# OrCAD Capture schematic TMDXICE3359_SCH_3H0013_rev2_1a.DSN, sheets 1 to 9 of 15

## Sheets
1 P13_Host Expansion & MMC0 & LCD: size C; title: TMDXICE3359; rev: 2.0A; company: Texas Instruments; note: AM335X_ICE_3H0013_2V0A.dsn; note: ARM MPU BU; note: 12500 TI BLVD MS8638
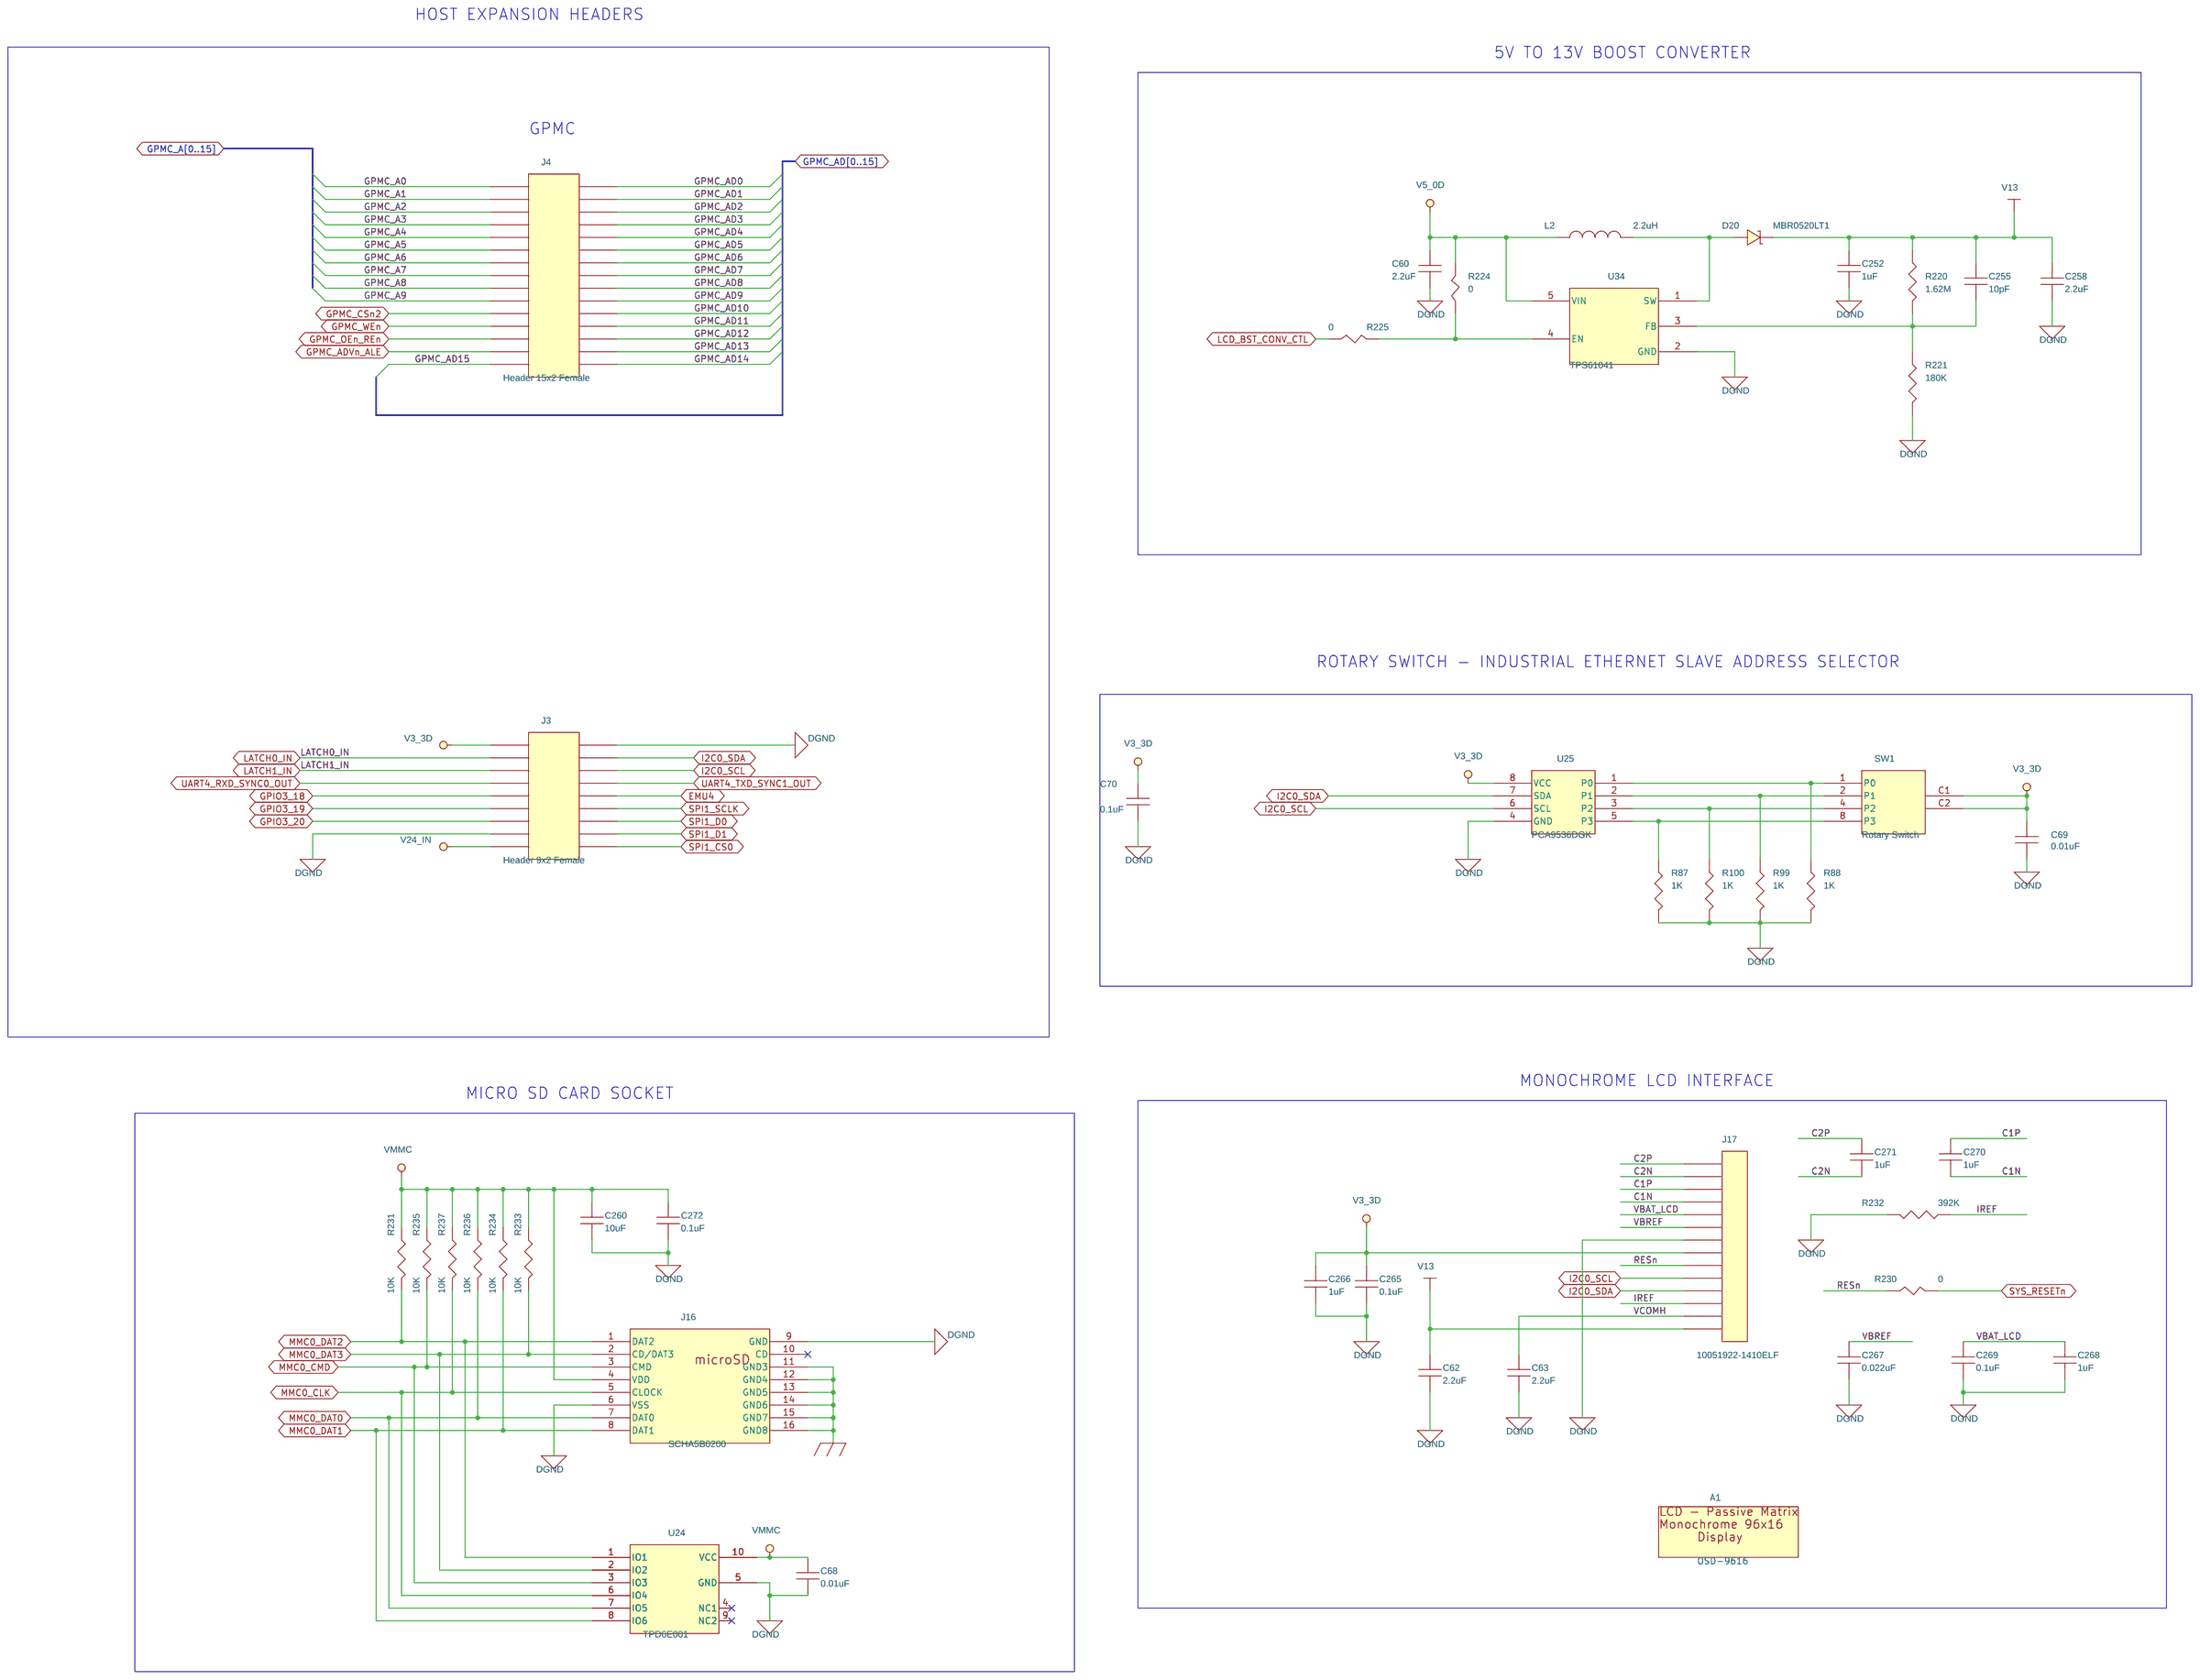
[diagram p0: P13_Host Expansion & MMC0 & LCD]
2 P12_Ethernet1: size C
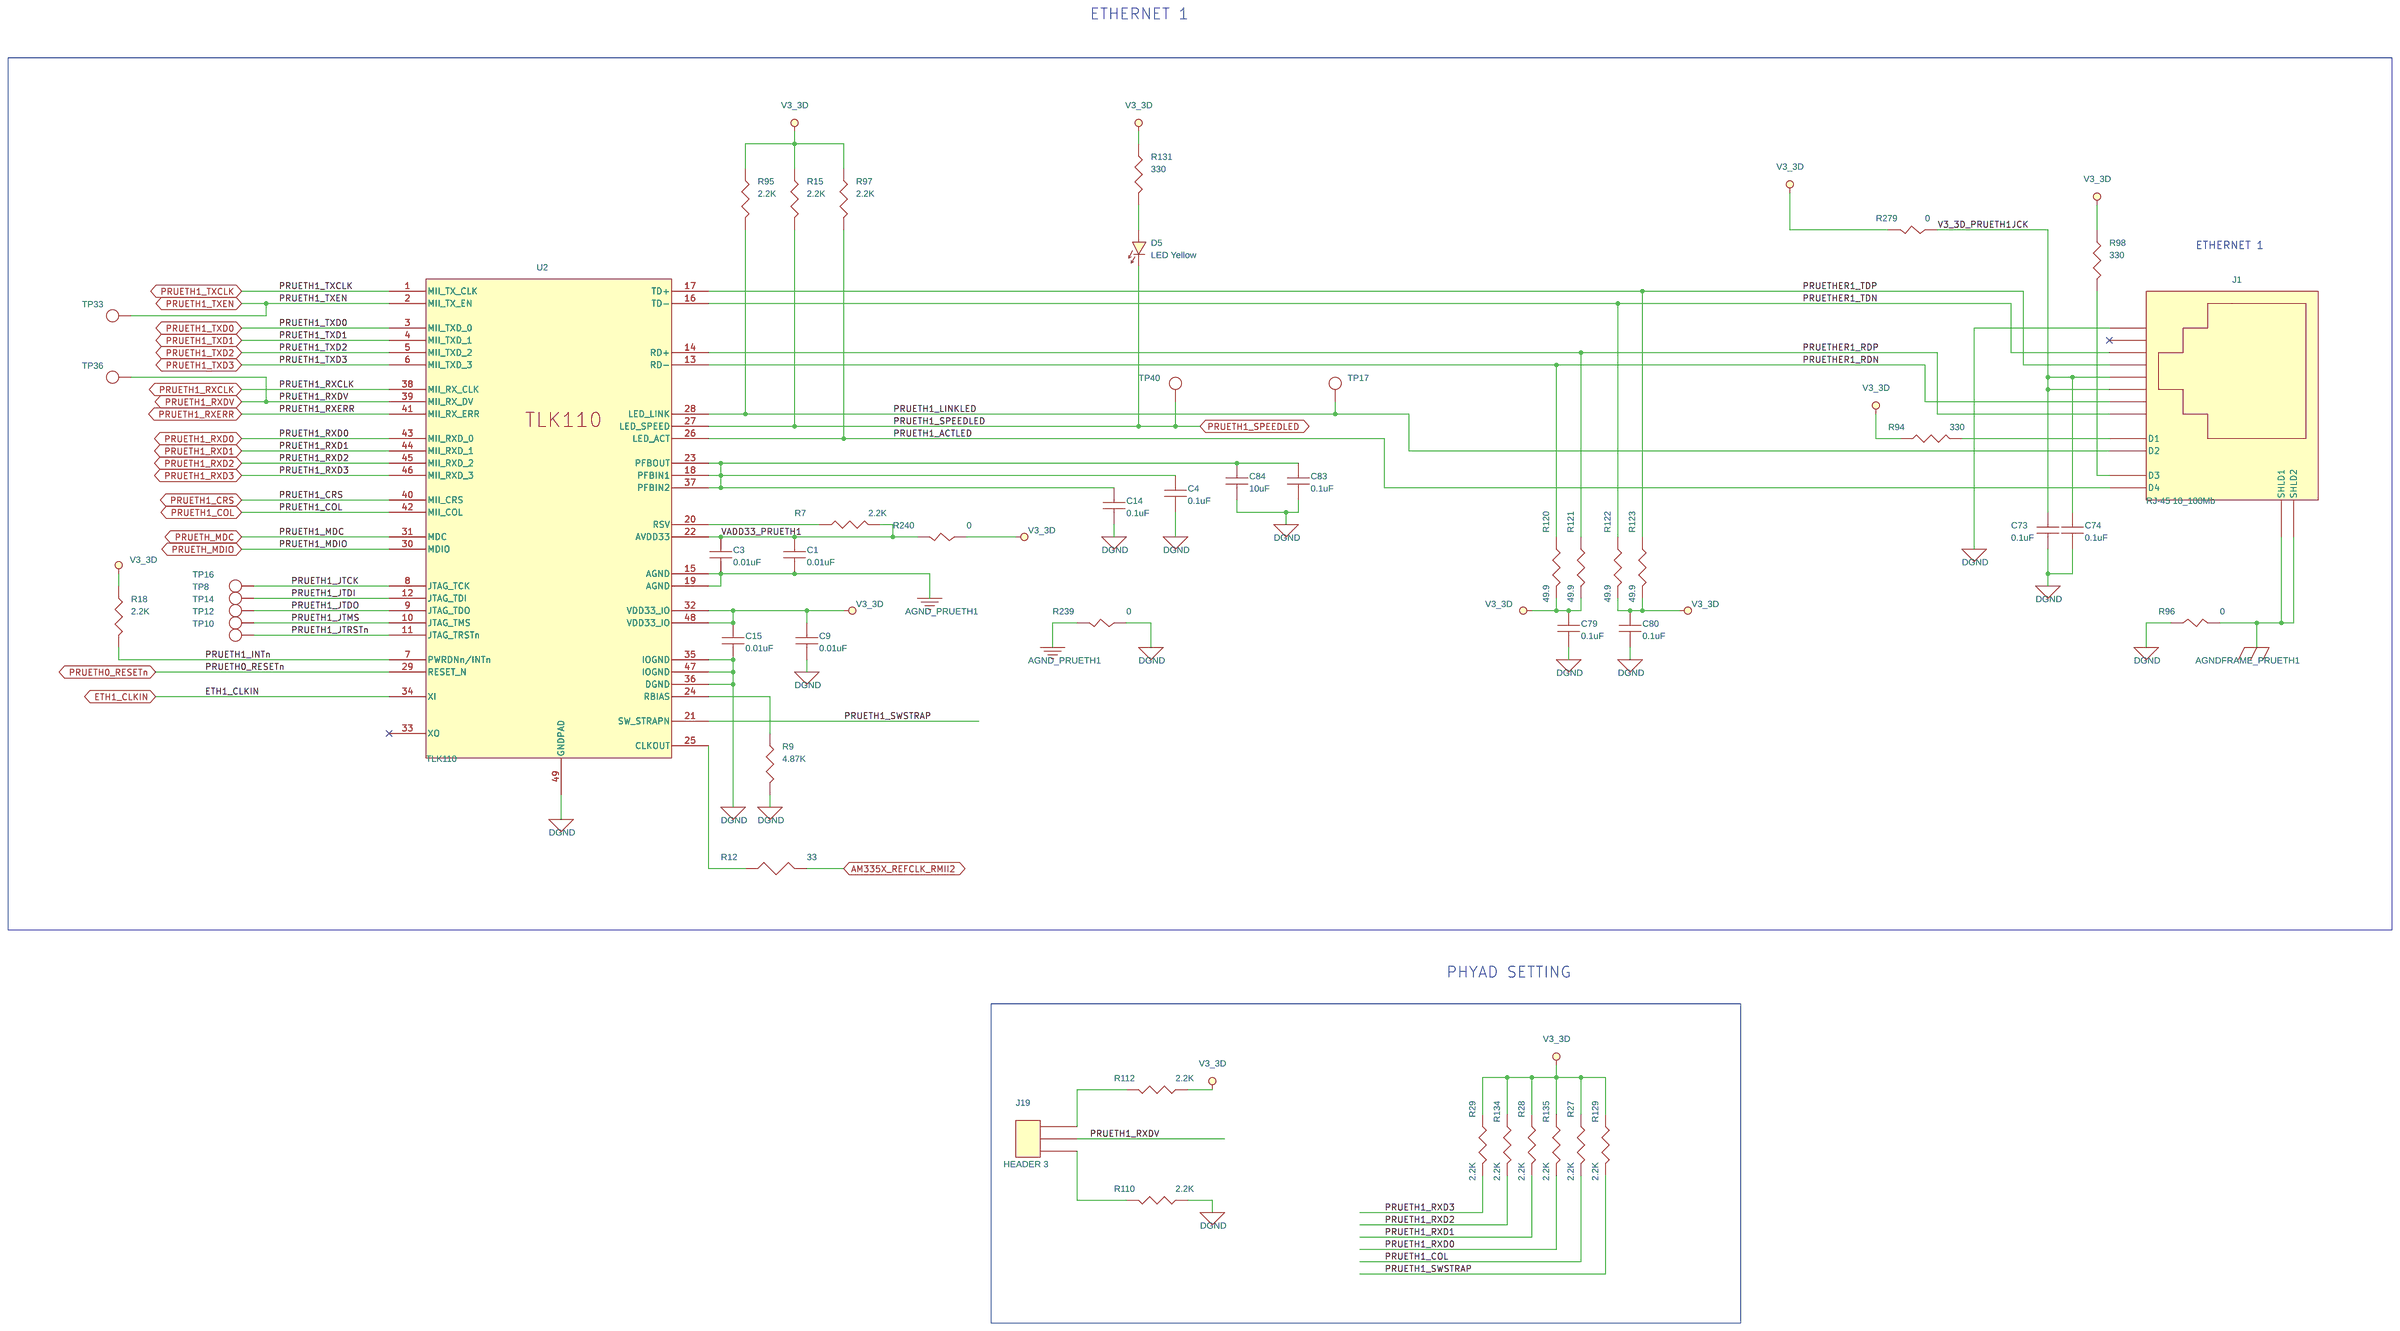
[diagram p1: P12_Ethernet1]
3 P11_Ethernet0: size C
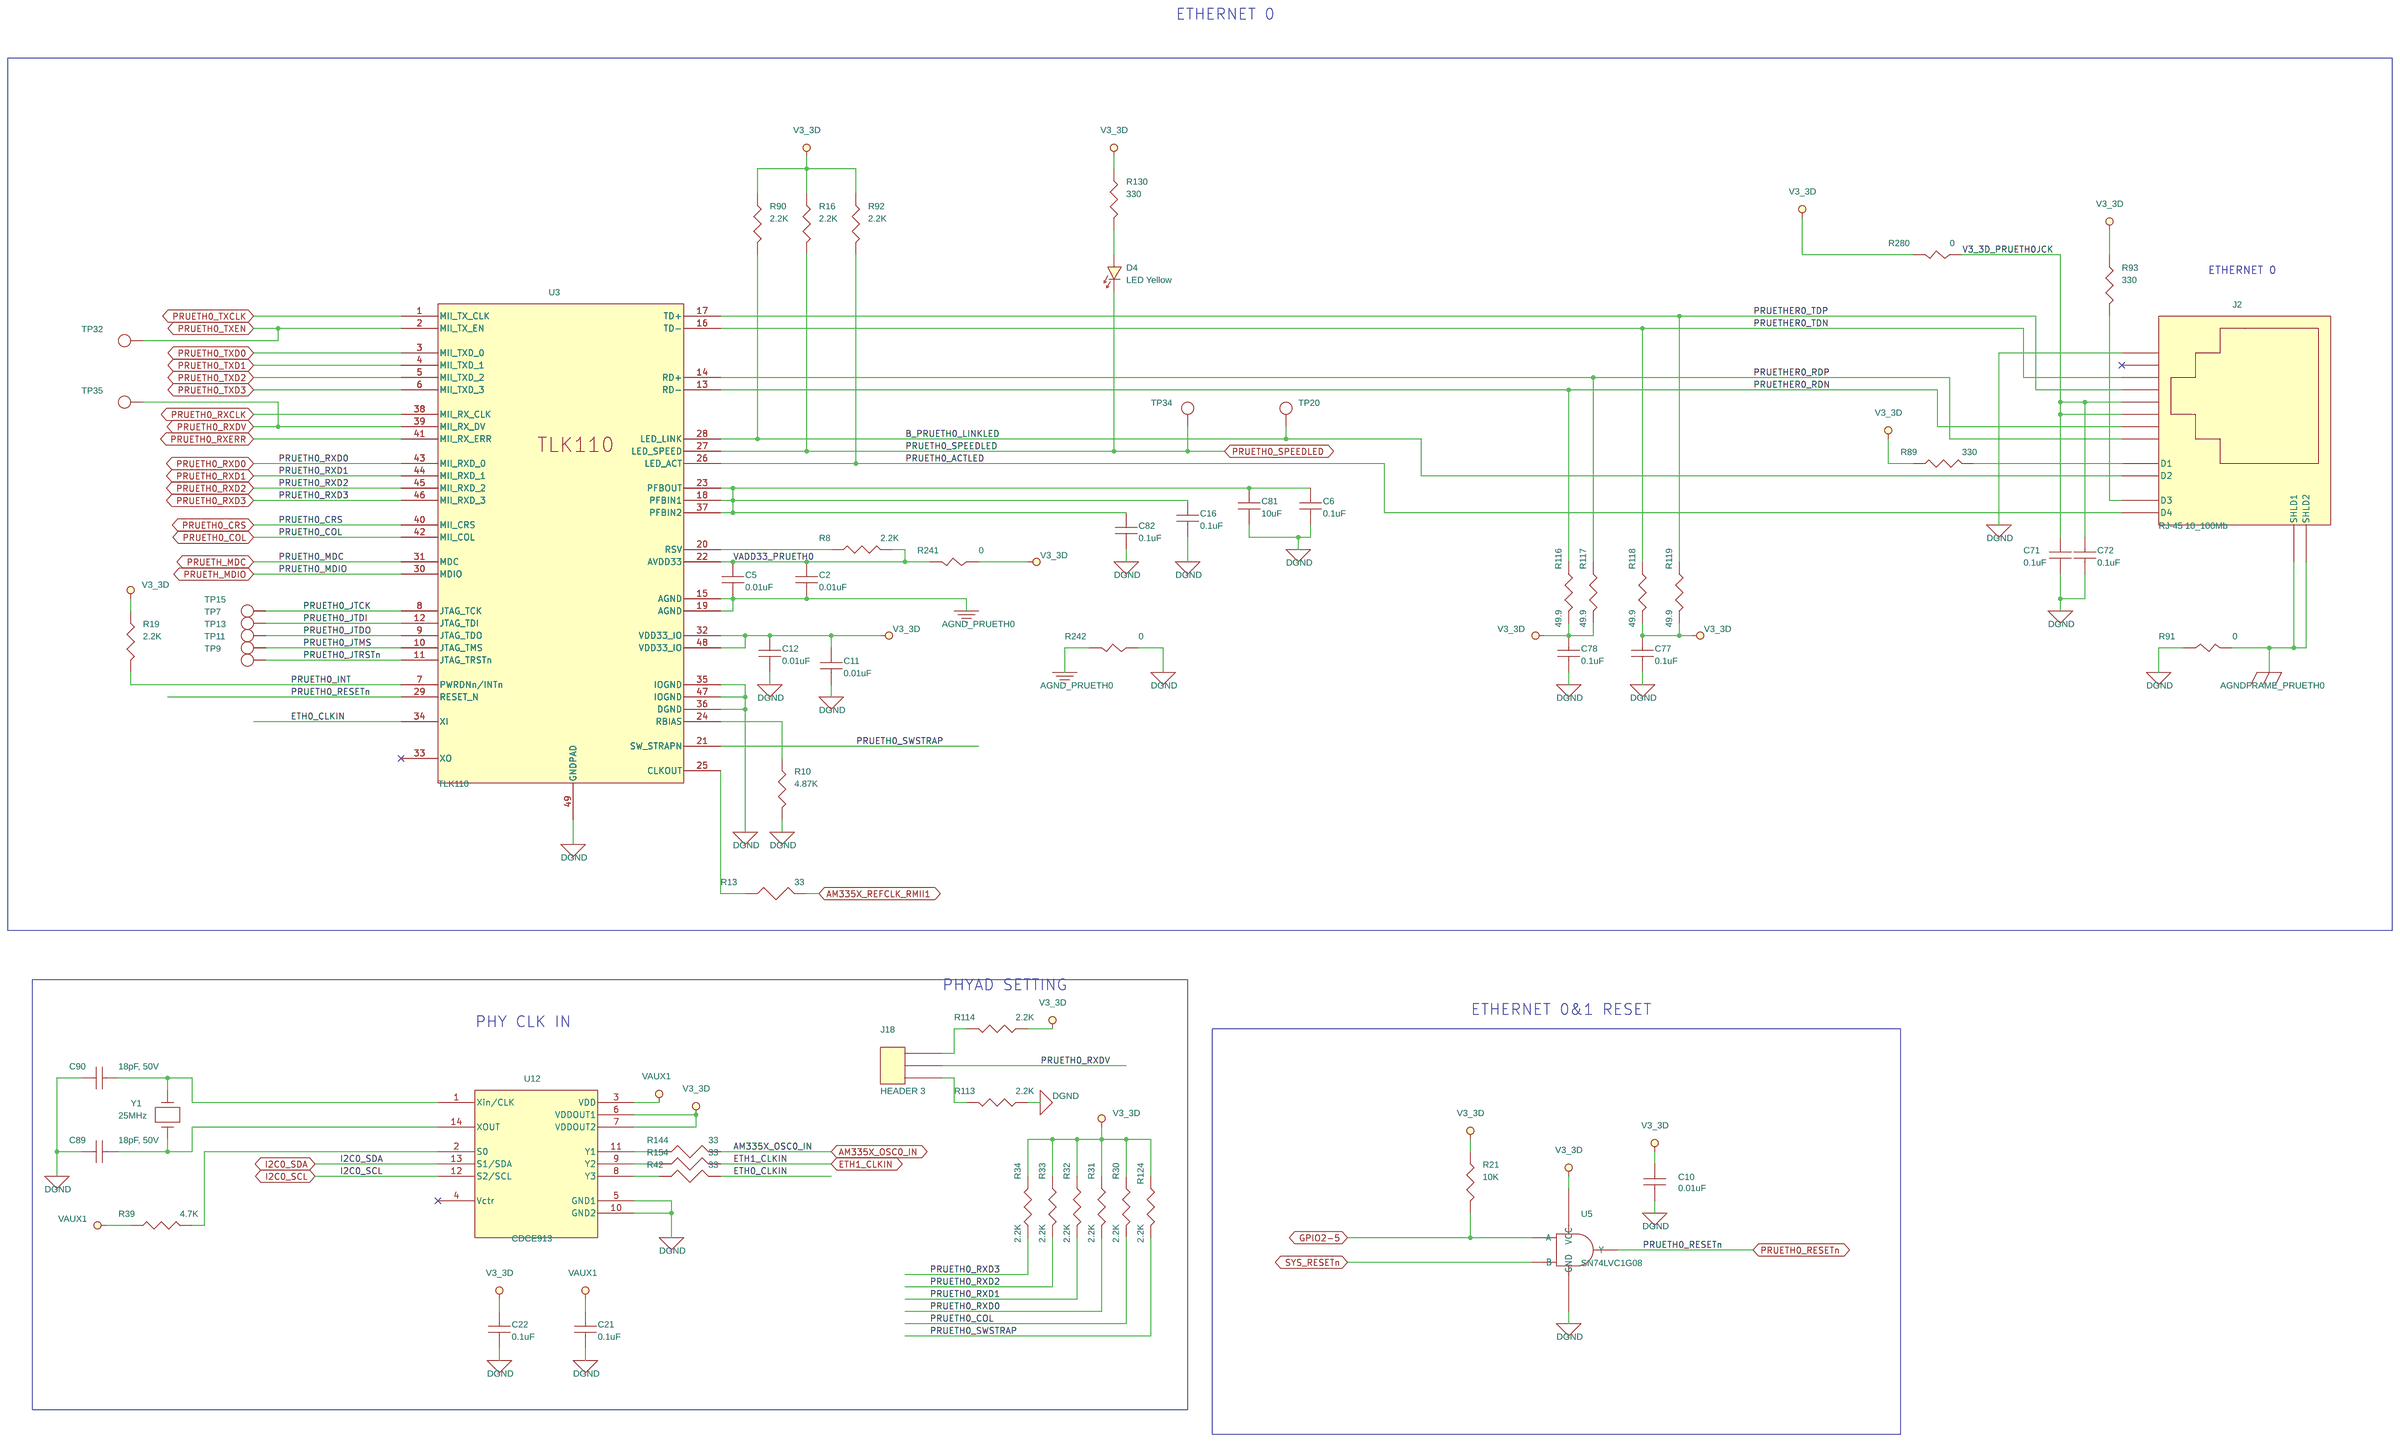
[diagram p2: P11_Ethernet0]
4 P10_PRU_CPSW_ETHERNET_MUX: size C
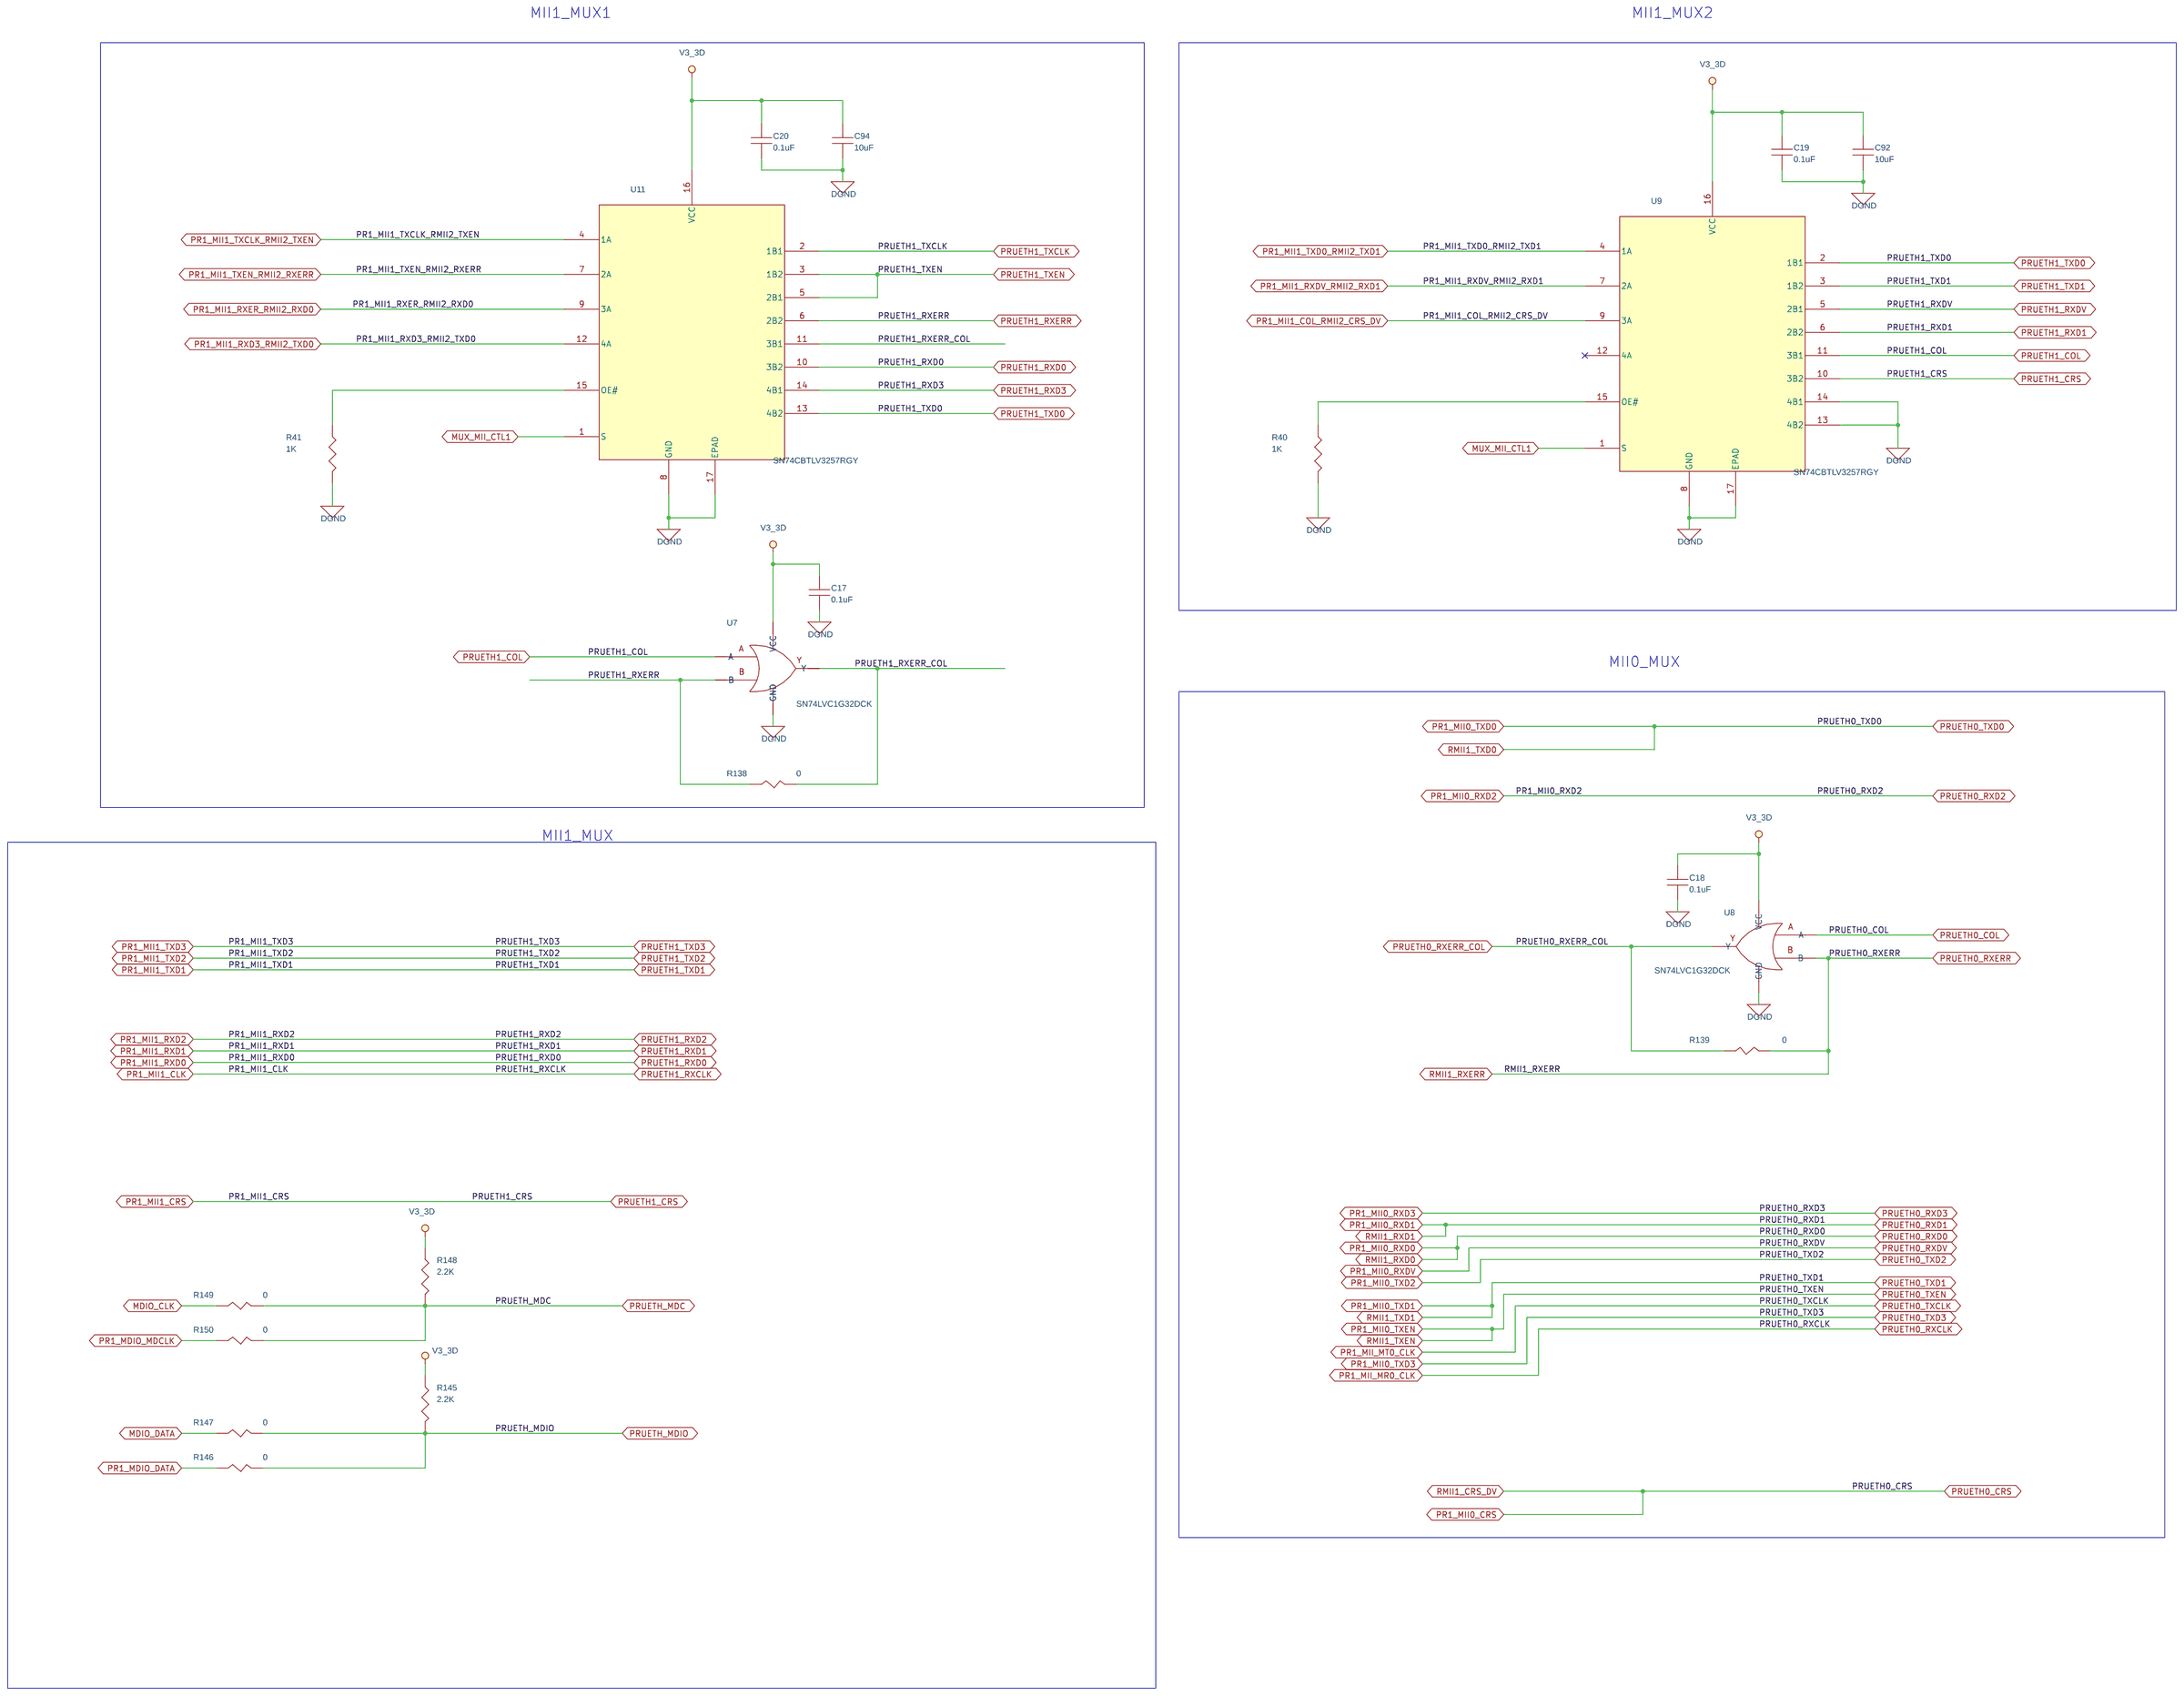
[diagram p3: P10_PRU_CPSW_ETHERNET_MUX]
5 P09_CAN & PROFI BUS: size C
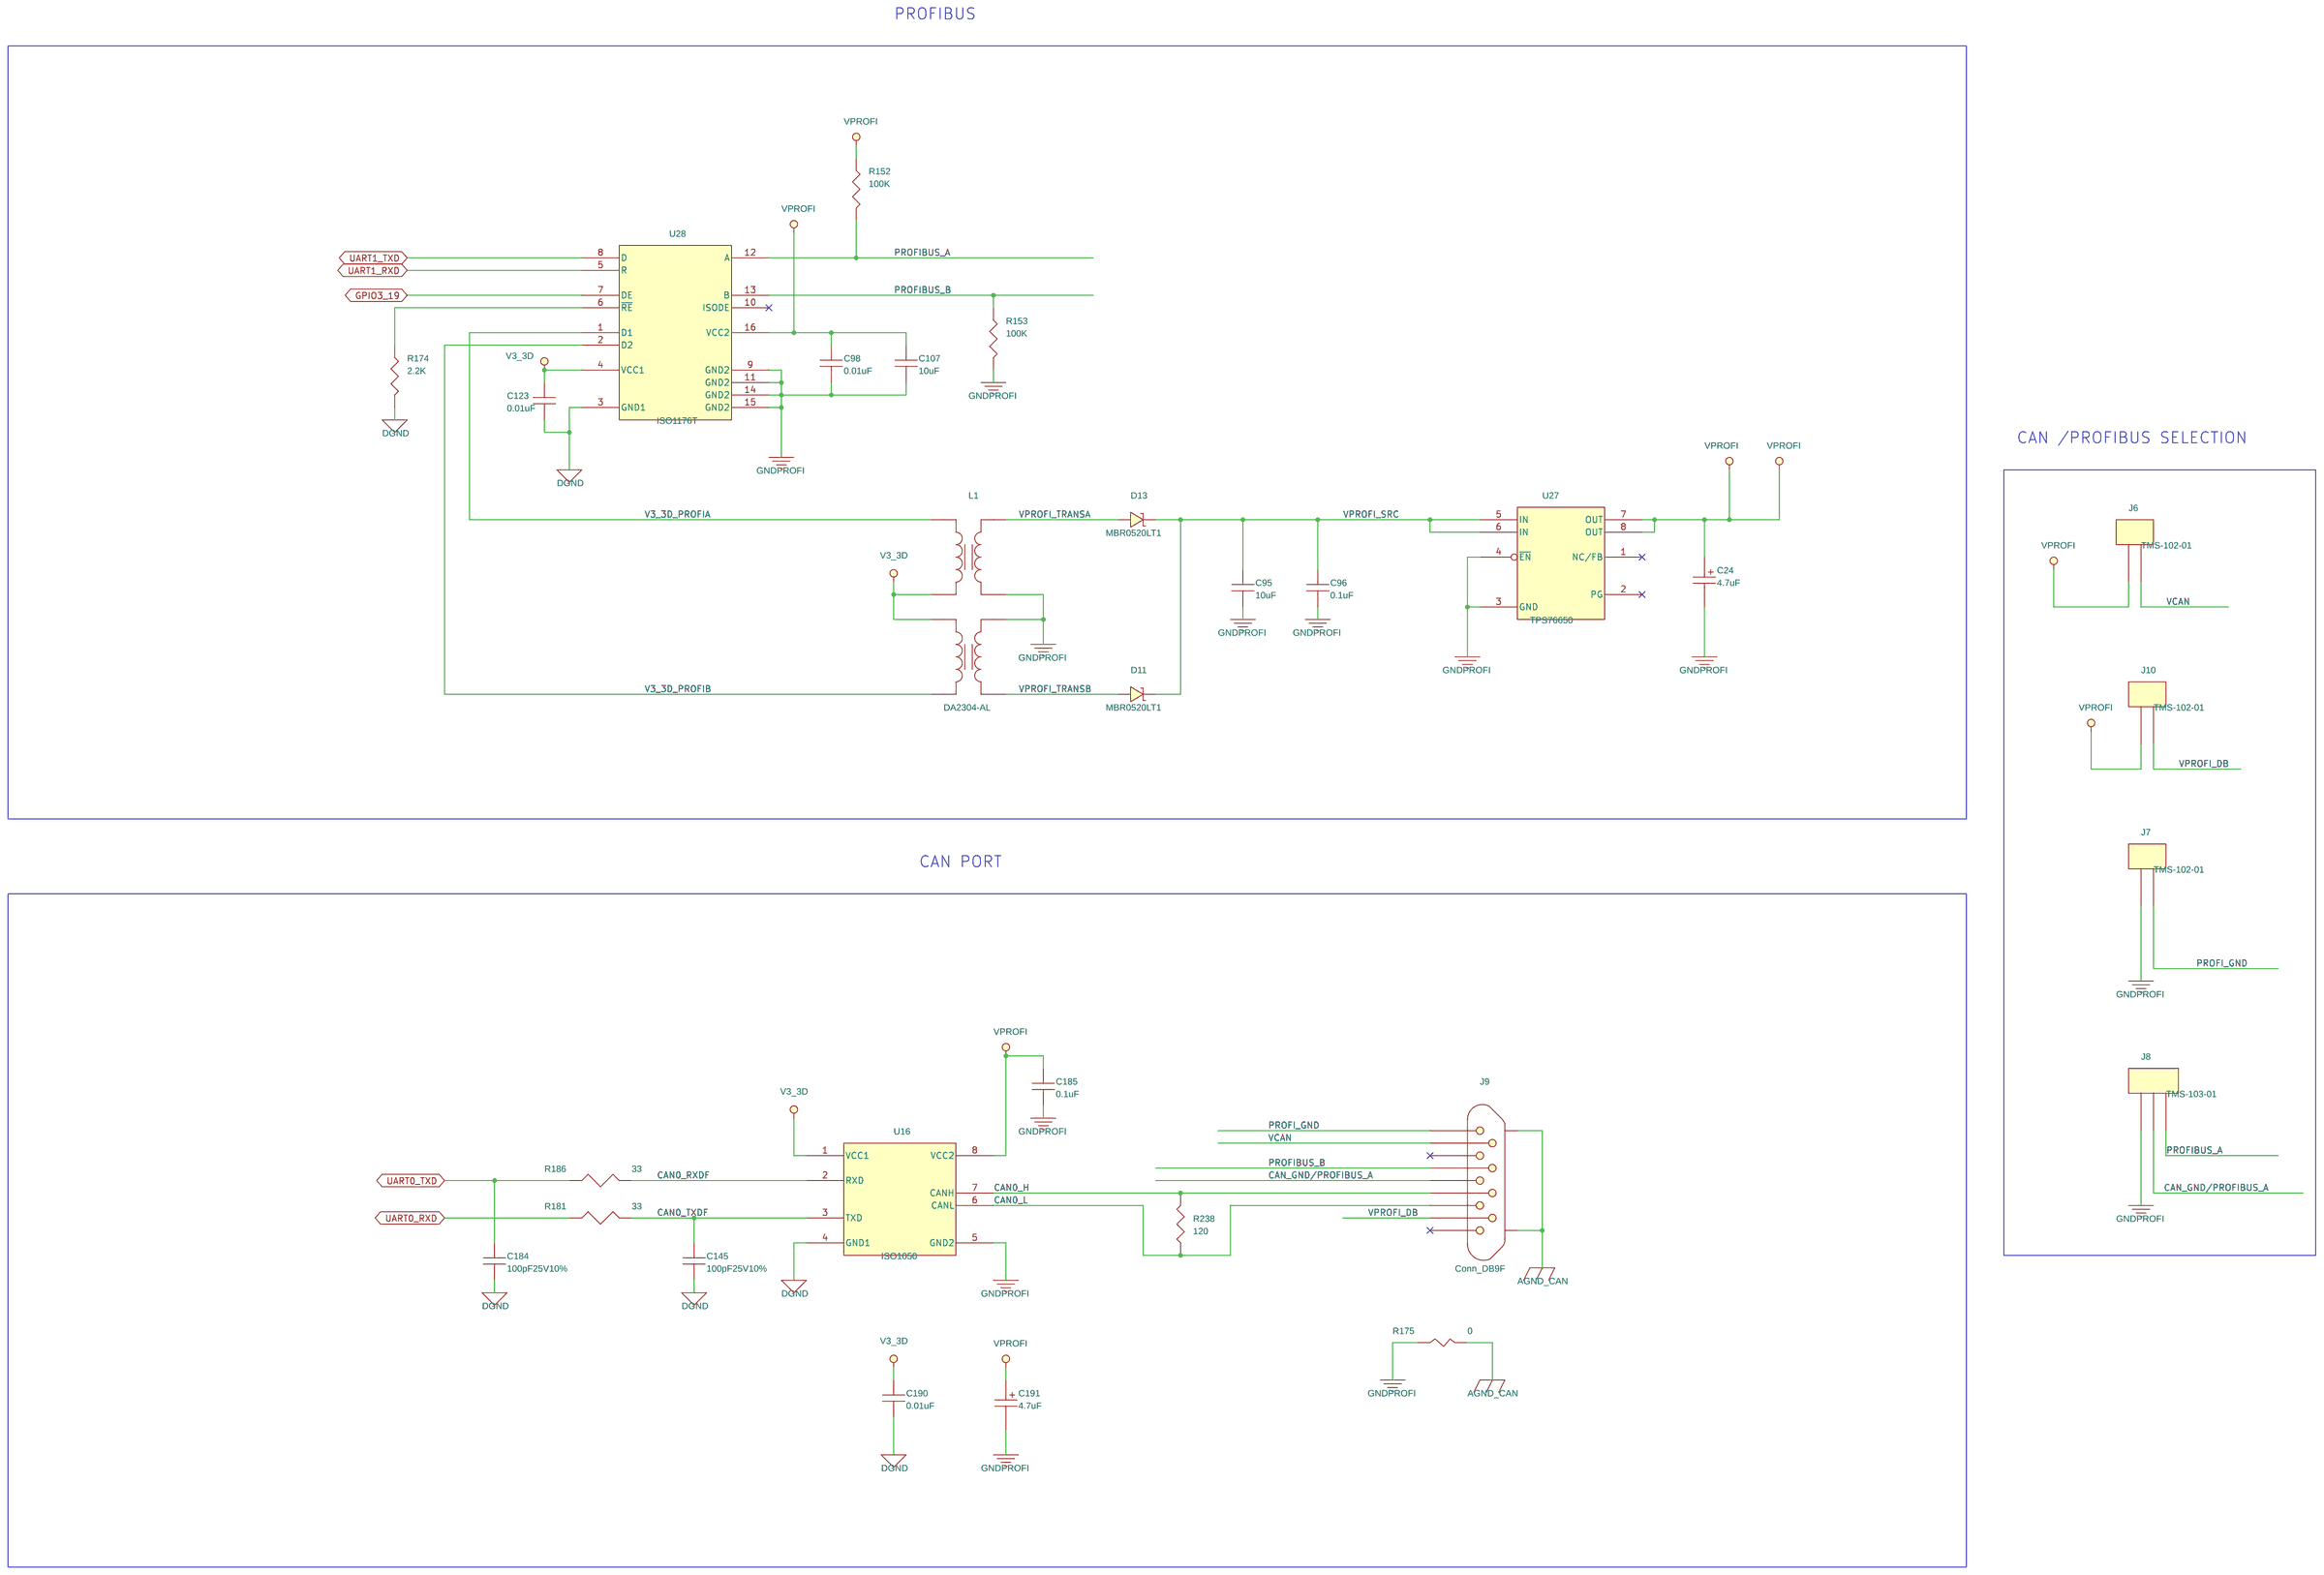
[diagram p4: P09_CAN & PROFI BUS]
6 P08_NOR_FLASH: size C
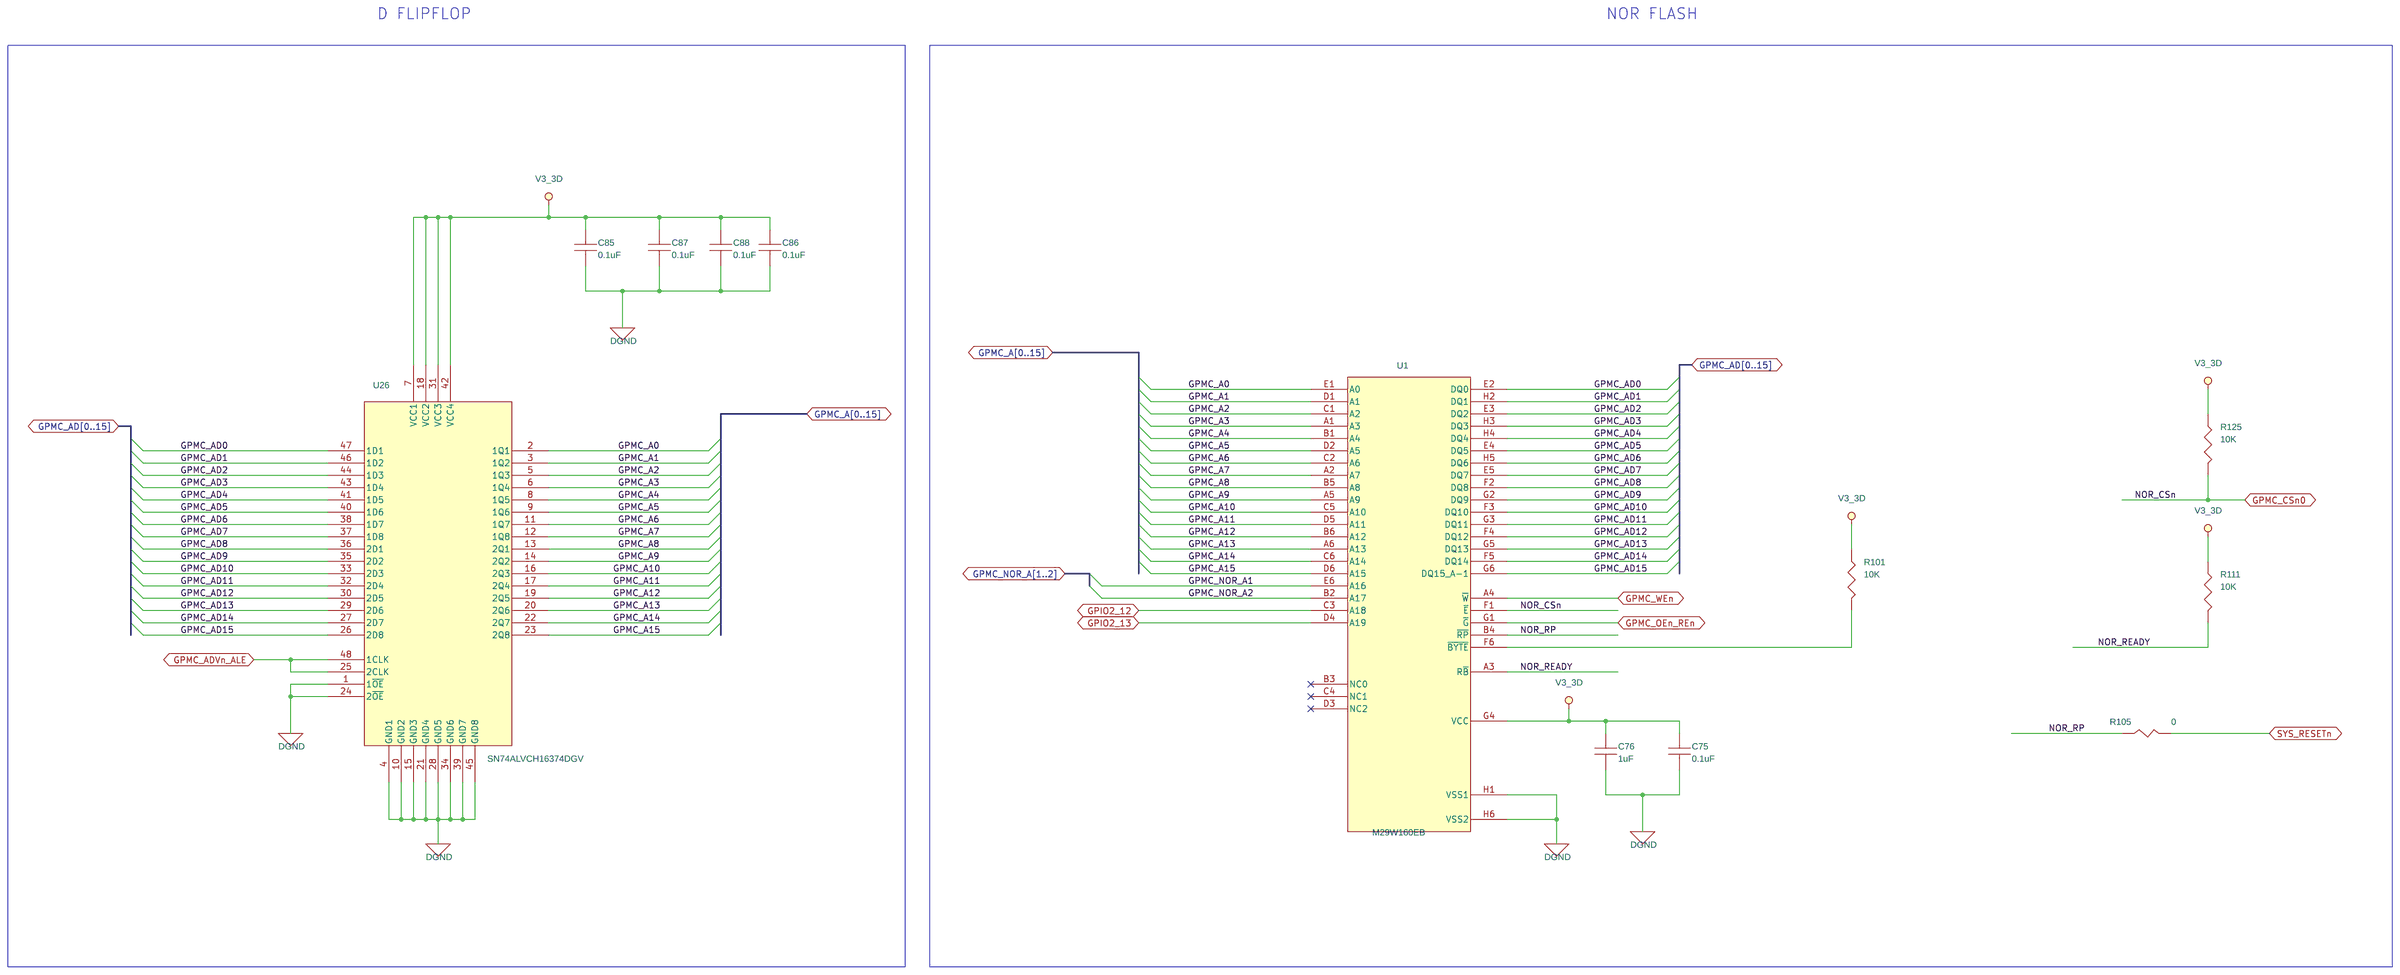
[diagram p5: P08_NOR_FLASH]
7 P07_DDR3_Memory: size C
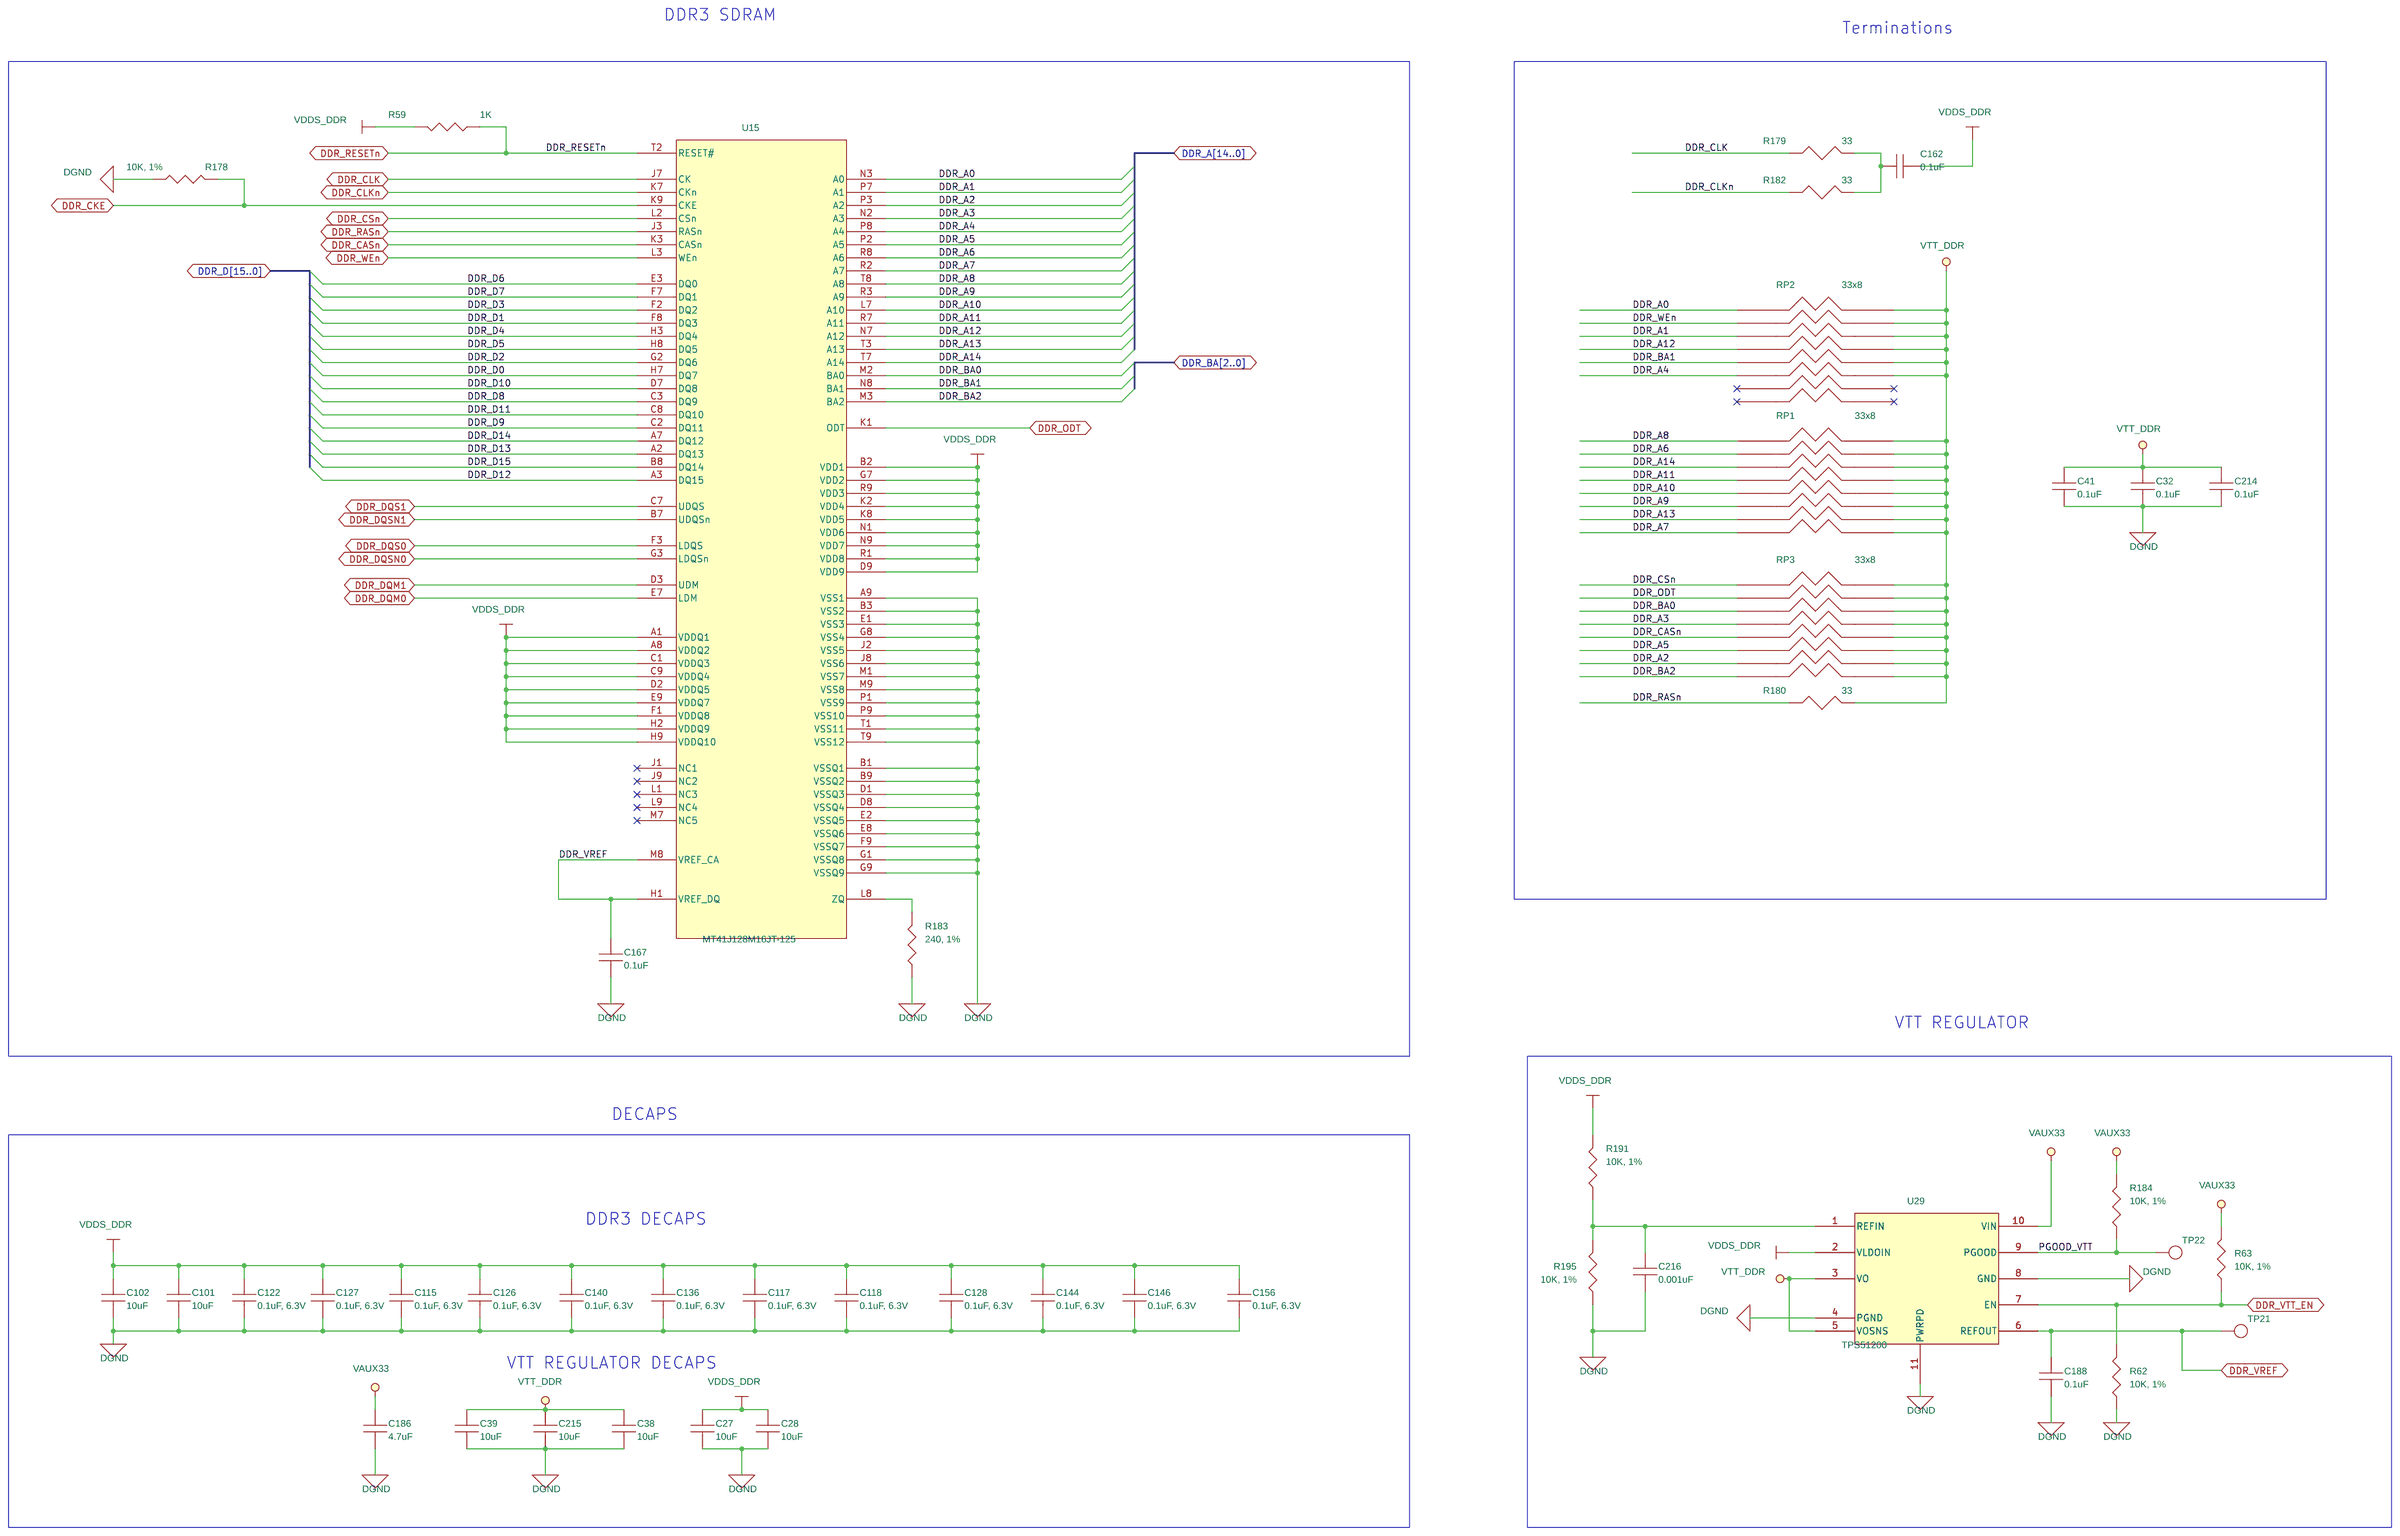
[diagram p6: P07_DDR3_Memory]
8 P06_SYSBOOT CONFG_ETHERCAT LEDS: size C
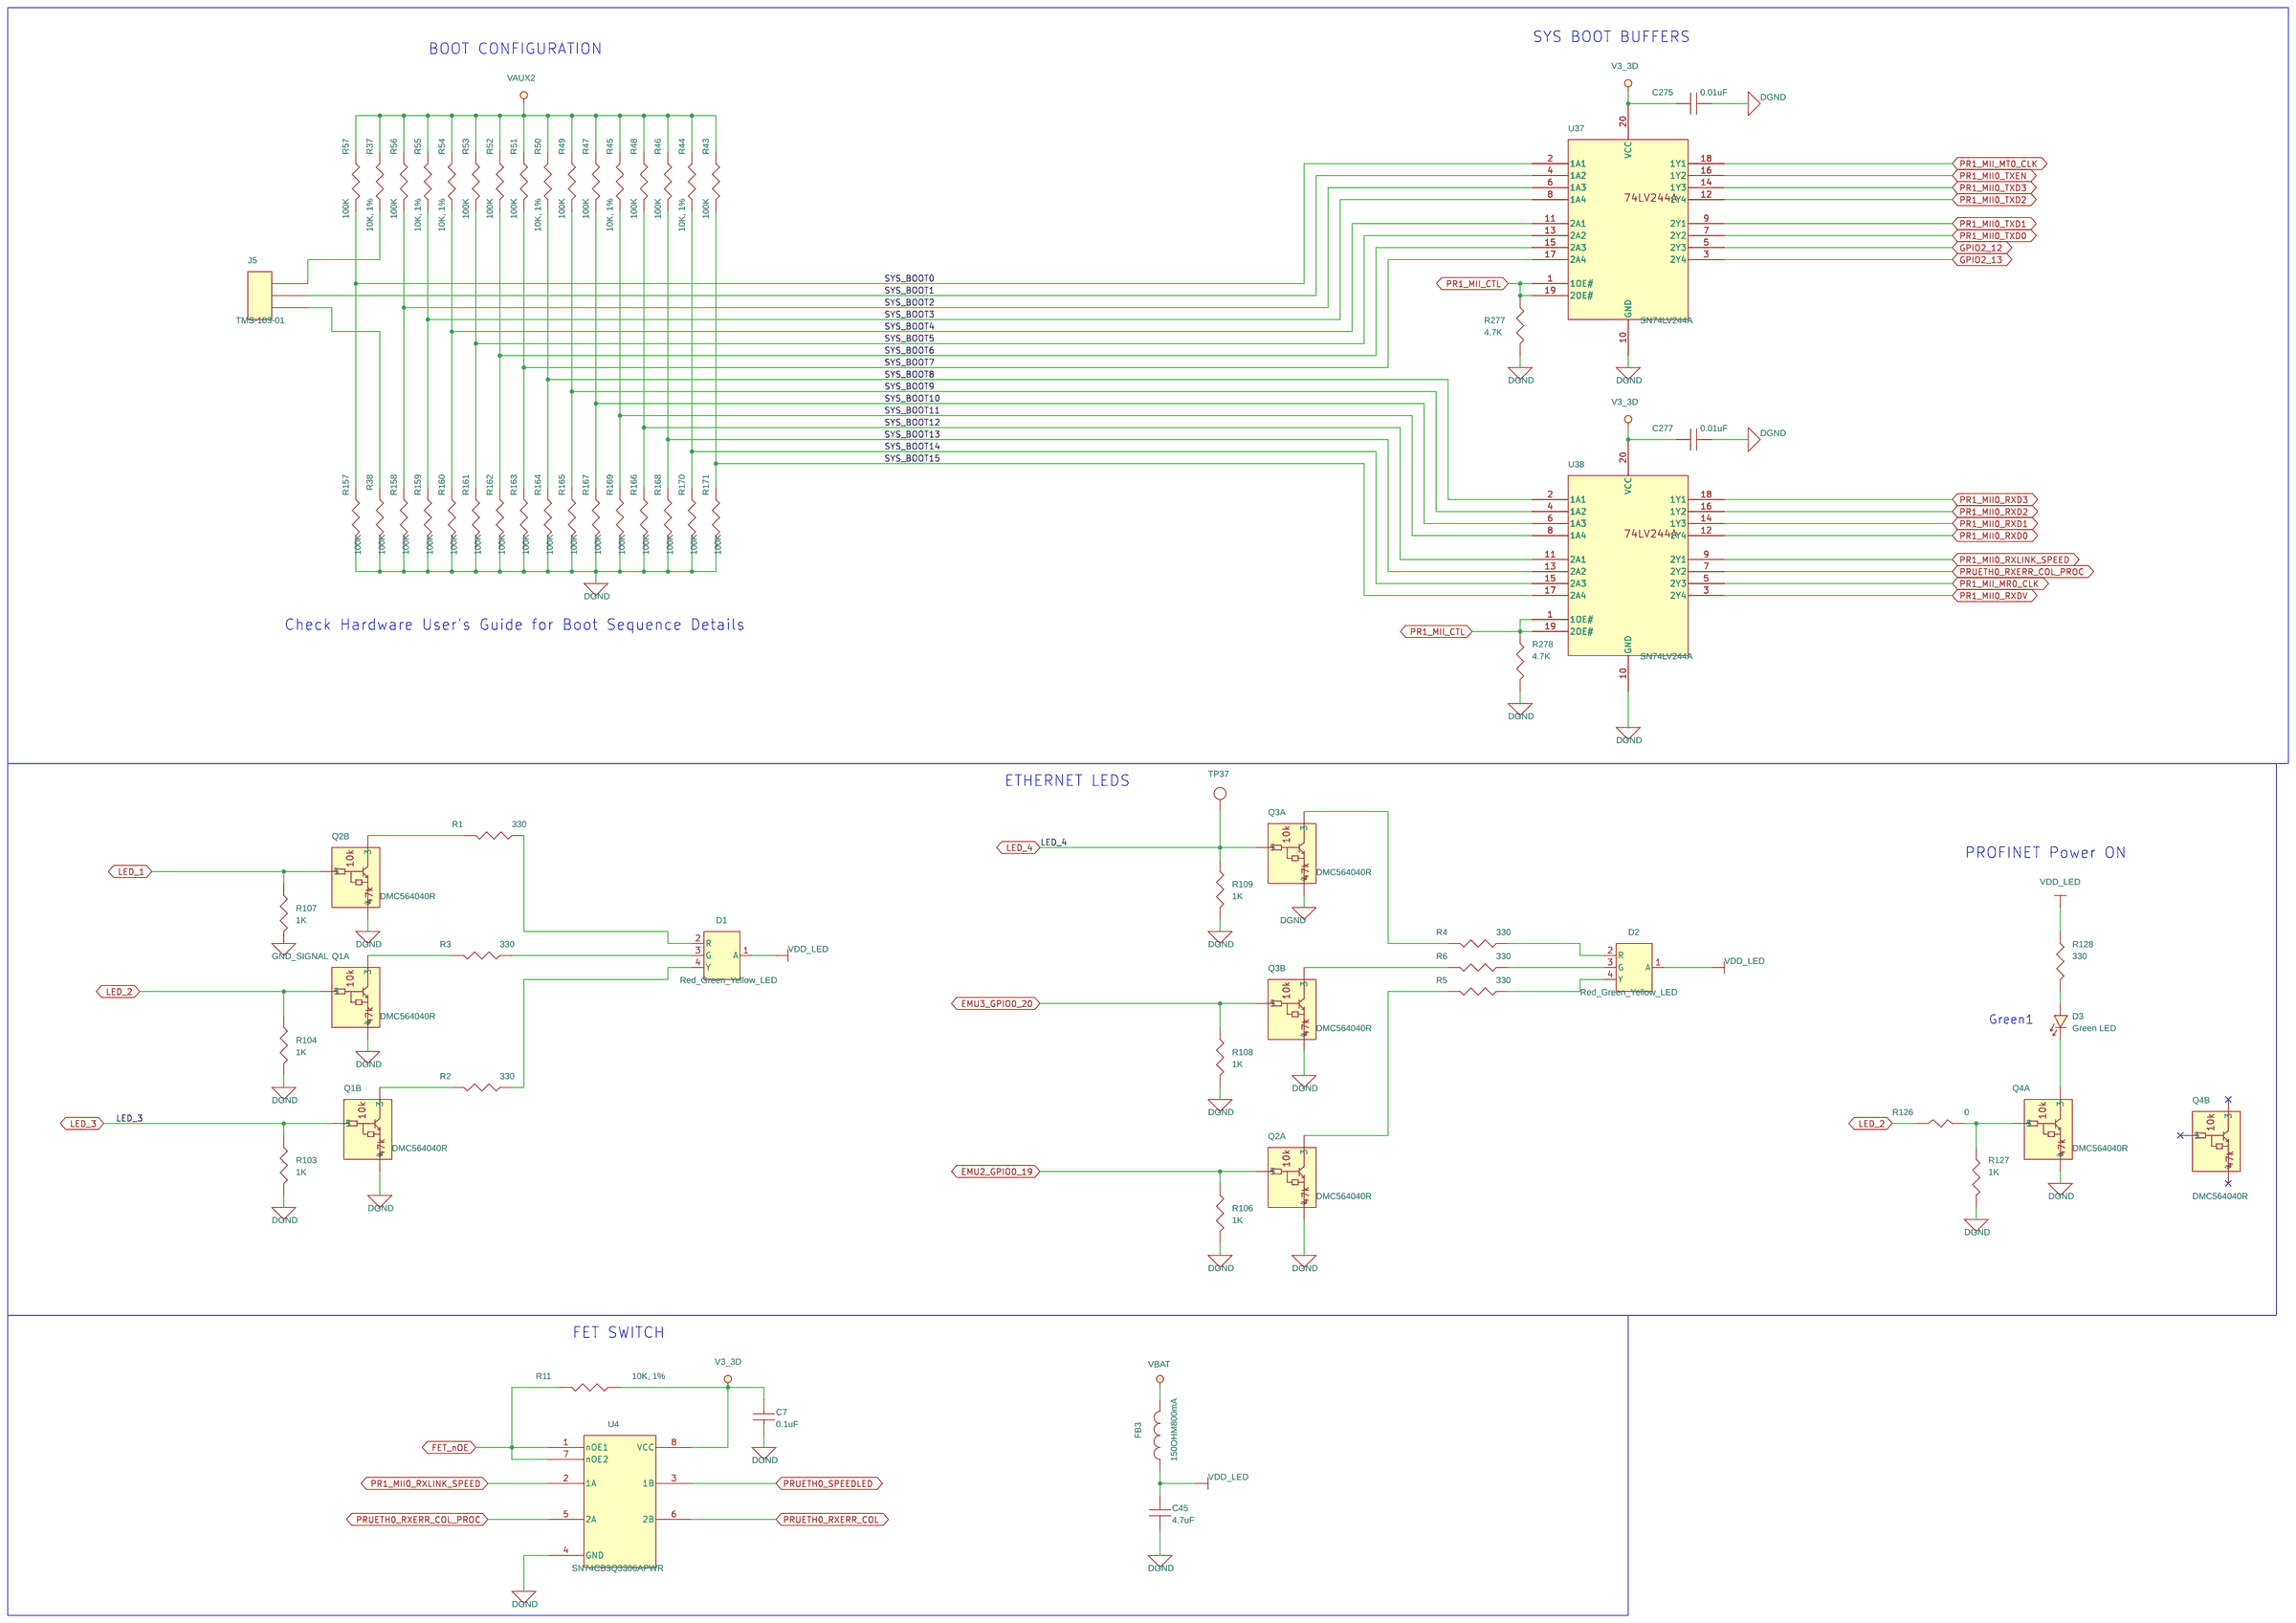
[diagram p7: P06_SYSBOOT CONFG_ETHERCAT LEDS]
9 P05_AM335x Page 3 of 3: size C
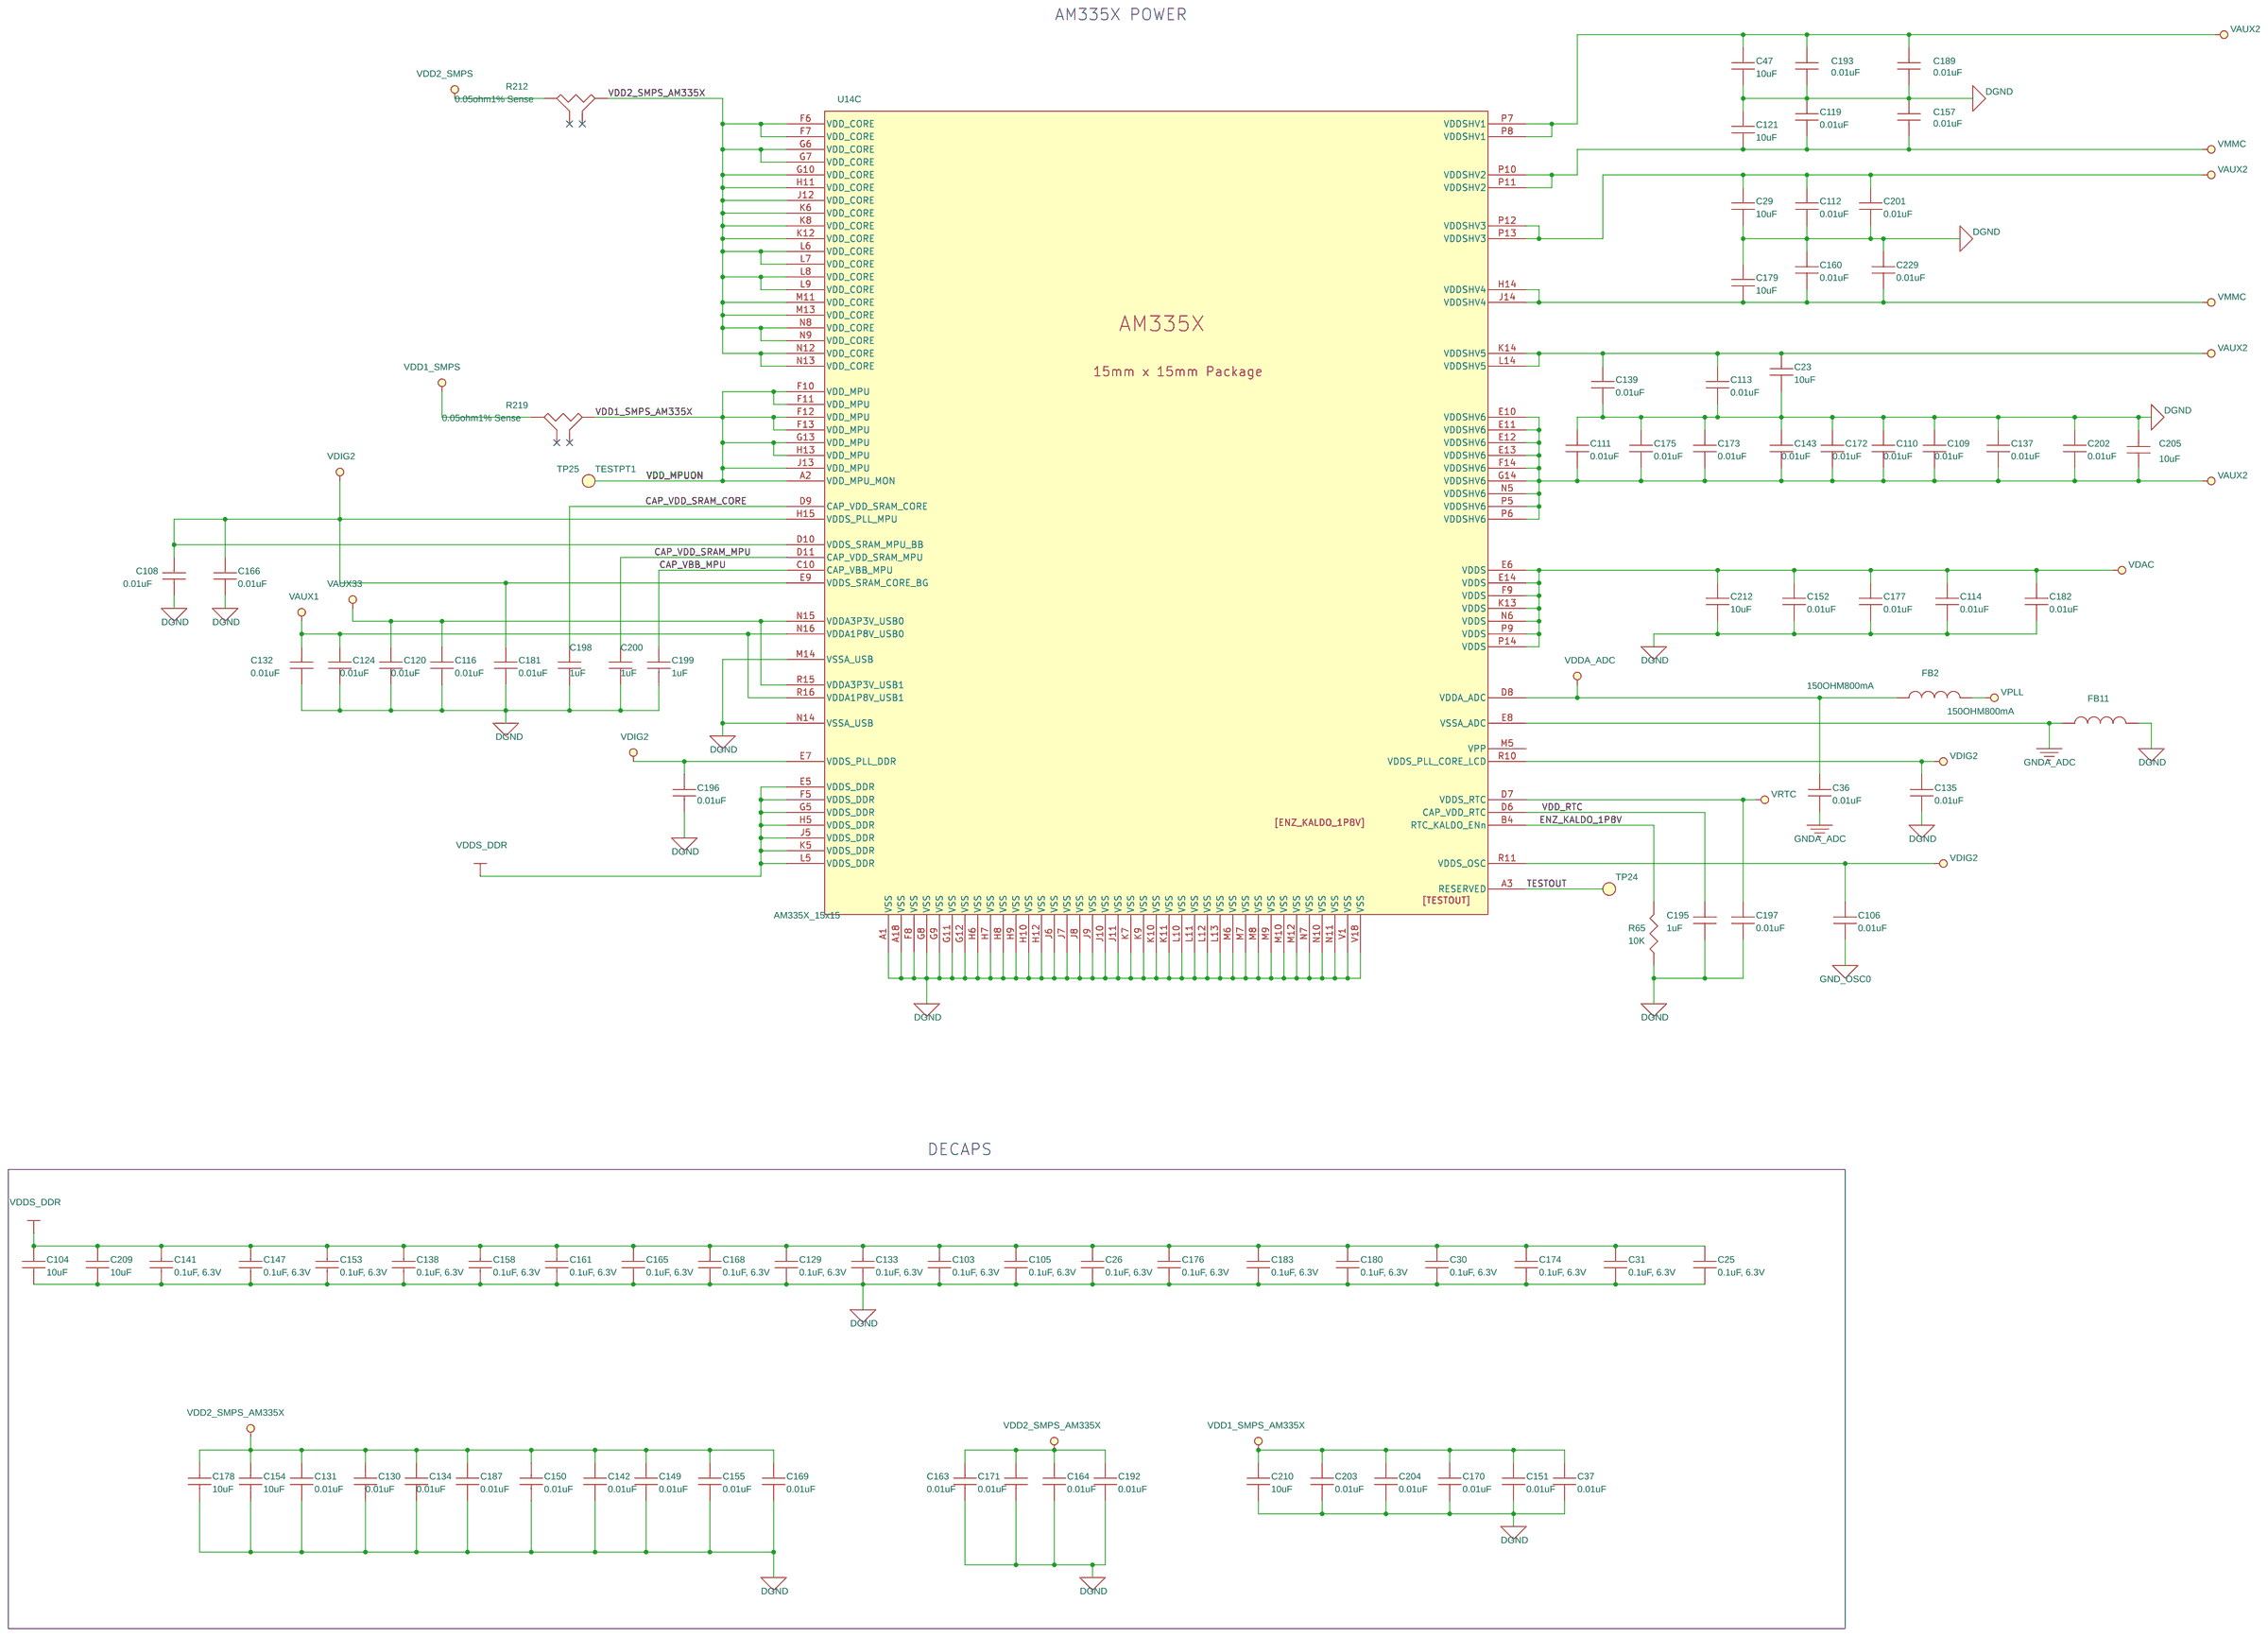
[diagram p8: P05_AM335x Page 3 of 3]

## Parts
sheet P05_AM335x Page 3 of 3
C23  10uF  [SM-7351-CAP-0805]
C25  0.1uF, 6.3V  [SMD0201]
C26  0.1uF, 6.3V  [SMD0201]
C29  10uF  [SM-7351-CAP-0805]
C30  0.1uF, 6.3V  [SMD0201]
C31  0.1uF, 6.3V  [SMD0201]
C36  0.01uF  [SM-7351-CAP-0402]
C37  0.01uF  [SM-7351-CAP-0402]
C47  10uF  [SM-7351-CAP-0805]
C103  0.1uF, 6.3V  [SMD0201]
C104  10uF  [SM-7351-CAP-0805]
C105  0.1uF, 6.3V  [SMD0201]
C106  0.01uF  [SM-7351-CAP-0402]
C108  0.01uF  [SM-7351-CAP-0402]
C109  0.01uF  [SM-7351-CAP-0402]
C110  0.01uF  [SM-7351-CAP-0402]
C111  0.01uF  [SM-7351-CAP-0402]
C112  0.01uF  [SM-7351-CAP-0402]
C113  0.01uF  [SM-7351-CAP-0402]
C114  0.01uF  [SM-7351-CAP-0402]
C116  0.01uF  [SM-7351-CAP-0402]
C119  0.01uF  [SM-7351-CAP-0402]
C120  0.01uF  [SM-7351-CAP-0402]
C121  10uF  [SM-7351-CAP-0805]
C124  0.01uF  [SM-7351-CAP-0402]
C129  0.1uF, 6.3V  [SMD0201]
C130  0.01uF  [SM-7351-CAP-0402]
C131  0.01uF  [SM-7351-CAP-0402]
C132  0.01uF  [SM-7351-CAP-0402]
C133  0.1uF, 6.3V  [SMD0201]
C134  0.01uF  [SM-7351-CAP-0402]
C135  0.01uF  [SM-7351-CAP-0402]
C137  0.01uF  [SM-7351-CAP-0402]
C138  0.1uF, 6.3V  [SMD0201]
C139  0.01uF  [SM-7351-CAP-0402]
C141  0.1uF, 6.3V  [SMD0201]
C142  0.01uF  [SM-7351-CAP-0402]
C143  0.01uF  [SM-7351-CAP-0402]
C147  0.1uF, 6.3V  [SMD0201]
C149  0.01uF  [SM-7351-CAP-0402]
C150  0.01uF  [SM-7351-CAP-0402]
C151  0.01uF  [SM-7351-CAP-0402]
C152  0.01uF  [SM-7351-CAP-0402]
C153  0.1uF, 6.3V  [SMD0201]
C154  10uF  [SM-7351-CAP-0805]
C155  0.01uF  [SM-7351-CAP-0402]
C157  0.01uF  [SM-7351-CAP-0402]
C158  0.1uF, 6.3V  [SMD0201]
C160  0.01uF  [SM-7351-CAP-0402]
C161  0.1uF, 6.3V  [SMD0201]
C163  0.01uF  [SM-7351-CAP-0402]
C164  0.01uF  [SM-7351-CAP-0402]
C165  0.1uF, 6.3V  [SMD0201]
C166  0.01uF  [SM-7351-CAP-0402]
C168  0.1uF, 6.3V  [SMD0201]
C169  0.01uF  [SM-7351-CAP-0402]
C170  0.01uF  [SM-7351-CAP-0402]
C171  0.01uF  [SM-7351-CAP-0402]
C172  0.01uF  [SM-7351-CAP-0402]
C173  0.01uF  [SM-7351-CAP-0402]
C174  0.1uF, 6.3V  [SMD0201]
C175  0.01uF  [SM-7351-CAP-0402]
C176  0.1uF, 6.3V  [SMD0201]
C177  0.01uF  [SM-7351-CAP-0402]
C178  10uF  [SM-7351-CAP-0805]
C179  10uF  [SM-7351-CAP-0805]
C180  0.1uF, 6.3V  [SMD0201]
C181  0.01uF  [SM-7351-CAP-0402]
C182  0.01uF  [SM-7351-CAP-0402]
C183  0.1uF, 6.3V  [SMD0201]
C187  0.01uF  [SM-7351-CAP-0402]
C189  0.01uF  [SM-7351-CAP-0402]
C192  0.01uF  [SM-7351-CAP-0402]
C193  0.01uF  [SM-7351-CAP-0402]
C195  1uF  [SM-7351-CAP-0402]
C196  0.01uF  [SM-7351-CAP-0402]
C197  0.01uF  [SM-7351-CAP-0402]
C198  1uF  [SM-7351-CAP-0402]
C199  1uF  [SM-7351-CAP-0402]
C200  1uF  [SM-7351-CAP-0402]
C201  0.01uF  [SM-7351-CAP-0402]
C202  0.01uF  [SM-7351-CAP-0402]
C203  0.01uF  [SM-7351-CAP-0402]
C204  0.01uF  [SM-7351-CAP-0402]
C205  10uF  [SM-7351-CAP-0805]
C209  10uF  [SM-7351-CAP-0805]
C210  10uF  [SM-7351-CAP-0805]
C212  10uF  [SM-7351-CAP-0805]
C229  0.01uF  [SM-7351-CAP-0402]
FB2  150OHM800mA  [sm-7351-ind-0805]
FB11  150OHM800mA  [sm-7351-ind-0805]
R65  10K  [SM-7351-RES-0402]
R212  0.05ohm1% Sense  [SM_RES_LVK12]
R219  0.05ohm1% Sense  [SM_RES_LVK12]
TP24  TESTPT1  [TP60C_SMD]
TP25  TESTPT1  [TP60C_SMD]
U14  AM335X_15x15  [am33xx_15x15]  (sections A,B,C)
sheet P06_SYSBOOT CONFG_ETHERCAT LEDS
C7  0.1uF  [SM-7351-CAP-0402]
C45  4.7uF  [SM-7351-CAP-0603]
C275  0.01uF  [SM-7351-CAP-0402]
C277  0.01uF  [SM-7351-CAP-0402]
D1  Red_Green_Yellow_LED  [LED-SM1210]
D2  Red_Green_Yellow_LED  [LED-SM1210]
D3  Green LED  [sm_led_0805]
FB3  150OHM800mA  [sm-7351-ind-0805]
J5  TMS-103-01  [SIP3_50LS]
Q1  DMC564040R  [SMINI6-F3-B]  (sections A,B)
Q2  DMC564040R  [SMINI6-F3-B]  (sections A,B)
Q3  DMC564040R  [SMINI6-F3-B]  (sections A,B)
Q4  DMC564040R  [SMINI6-F3-B]  (sections A,B)
R1  330  [SM-7351-RES-0402]
R2  330  [SM-7351-RES-0402]
R3  330  [SM-7351-RES-0402]
R4  330  [SM-7351-RES-0402]
R5  330  [SM-7351-RES-0402]
R6  330  [SM-7351-RES-0402]
R11  10K, 1%  [SM-7351-RES-0402]
R37  10K, 1%  [SM-7351-RES-0402]
R38  100K  [SM-7351-RES-0402]
R43  100K  [SM-7351-RES-0402]
R44  10K, 1%  [SM-7351-RES-0402]
R45  10K, 1%  [SM-7351-RES-0402]
R46  100K  [SM-7351-RES-0402]
R47  100K  [SM-7351-RES-0402]
R48  100K  [SM-7351-RES-0402]
R49  100K  [SM-7351-RES-0402]
R50  10K, 1%  [SM-7351-RES-0402]
R51  100K  [SM-7351-RES-0402]
R52  100K  [SM-7351-RES-0402]
R53  100K  [SM-7351-RES-0402]
R54  10K, 1%  [SM-7351-RES-0402]
R55  10K, 1%  [SM-7351-RES-0402]
R56  100K  [SM-7351-RES-0402]
R57  100K  [SM-7351-RES-0402]
R103  1K  [SM-7351-RES-0402]
R104  1K  [SM-7351-RES-0402]
R106  1K  [SM-7351-RES-0402]
R107  1K  [SM-7351-RES-0402]
R108  1K  [SM-7351-RES-0402]
R109  1K  [SM-7351-RES-0402]
R126  0  [SM-7351-RES-0402]
R127  1K  [SM-7351-RES-0402]
R128  330  [SM-7351-RES-0402]
R157  100K  [SM-7351-RES-0402]
R158  100K  [SM-7351-RES-0402]
R159  100K  [SM-7351-RES-0402]
R160  100K  [SM-7351-RES-0402]
R161  100K  [SM-7351-RES-0402]
R162  100K  [SM-7351-RES-0402]
R163  100K  [SM-7351-RES-0402]
R164  100K  [SM-7351-RES-0402]
R165  100K  [SM-7351-RES-0402]
R166  100K  [SM-7351-RES-0402]
R167  100K  [SM-7351-RES-0402]
R168  100K  [SM-7351-RES-0402]
R169  100K  [SM-7351-RES-0402]
R170  100K  [SM-7351-RES-0402]
R171  100K  [SM-7351-RES-0402]
R277  4.7K  [SM-7351-RES-0402]
R278  4.7K  [SM-7351-RES-0402]
TP37  TP1mm  [tp_smd1mmcircle]
U4  SN74CB3Q3306APWR  [PW8]
U37  SN74LV244A  [TSSOP4X6-20]
U38  SN74LV244A  [TSSOP4X6-20]
sheet P07_DDR3_Memory
C27  10uF  [SM-7351-CAP-0805]
C28  10uF  [SM-7351-CAP-0805]
C32  0.1uF  [SM-7351-CAP-0402]
C38  10uF  [SM-7351-CAP-0805]
C39  10uF  [SM-7351-CAP-0805]
C41  0.1uF  [SM-7351-CAP-0402]
C101  10uF  [SM-7351-CAP-0805]
C102  10uF  [SM-7351-CAP-0805]
C115  0.1uF, 6.3V  [SMD0201]
C117  0.1uF, 6.3V  [SMD0201]
C118  0.1uF, 6.3V  [SMD0201]
C122  0.1uF, 6.3V  [SMD0201]
C126  0.1uF, 6.3V  [SMD0201]
C127  0.1uF, 6.3V  [SMD0201]
C128  0.1uF, 6.3V  [SMD0201]
C136  0.1uF, 6.3V  [SMD0201]
C140  0.1uF, 6.3V  [SMD0201]
C144  0.1uF, 6.3V  [SMD0201]
C146  0.1uF, 6.3V  [SMD0201]
C156  0.1uF, 6.3V  [SMD0201]
C162  0.1uF  [SM-7351-CAP-0402]
C167  0.1uF  [SM-7351-CAP-0402]
C186  4.7uF  [SM-7351-CAP-0603]
C188  0.1uF  [SM-7351-CAP-0402]
C214  0.1uF  [SM-7351-CAP-0402]
C215  10uF  [SM-7351-CAP-0805]
C216  0.001uF  [SM-7351-CAP-0402]
R59  1K  [SM-7351-RES-0402]
R62  10K, 1%  [SM-7351-RES-0402]
R63  10K, 1%  [SM-7351-RES-0402]
R178  10K, 1%  [SM-7351-RES-0402]
R179  33  [SM-7351-RES-0402]
R180  33  [SM-7351-RES-0402]
R182  33  [SM-7351-RES-0402]
R183  240, 1%  [SM-7351-RES-0402]
R184  10K, 1%  [SM-7351-RES-0402]
R191  10K, 1%  [SM-7351-RES-0402]
R195  10K, 1%  [SM-7351-RES-0402]
RP1  33x8  [EXB-2HV330JV]
RP2  33x8  [EXB-2HV330JV]
RP3  33x8  [EXB-2HV330JV]
TP21  TP1mm  [tp_smd1mmcircle]
TP22  TP1mm  [tp_smd1mmcircle]
U15  MT41J128M16JT-125  [BGA14X10-96]
U29  TPS51200  [drcpso_10pin]
sheet P08_NOR_FLASH
C75  0.1uF  [SM-7351-CAP-0402]
C76  1uF  [SM-7351-CAP-0402]
C85  0.1uF  [SM-7351-CAP-0402]
C86  0.1uF  [SM-7351-CAP-0402]
C87  0.1uF  [SM-7351-CAP-0402]
C88  0.1uF  [SM-7351-CAP-0402]
R101  10K  [SM-7351-RES-0402]
R105  0  [SM-7351-RES-0402]
R111  10K  [SM-7351-RES-0402]
R125  10K  [SM-7351-RES-0402]
U1  M29W160EB  [TFBGA48]
U26  SN74ALVCH16374DGV  [TVSOP-48]
sheet P09_CAN & PROFI BUS
C24  4.7uF  [sm-7351-cap-0805]
C95  10uF  [SM-7351-CAP-0805]
C96  0.1uF  [SM-7351-CAP-0402]
C98  0.01uF  [SM-7351-CAP-0402]
C107  10uF  [SM-7351-CAP-0805]
C123  0.01uF  [SM-7351-CAP-0402]
C145  100pF25V10%  [SM-7351-CAP-0402]
C184  100pF25V10%  [SM-7351-CAP-0402]
C185  0.1uF  [SM-7351-CAP-0402]
C190  0.01uF  [SM-7351-CAP-0402]
C191  4.7uF  [sm-7351-cap-0805]
D11  MBR0520LT1  [mbr0520L]
D13  MBR0520LT1  [mbr0520L]
J6  TMS-102-01  [SIP2_50LS]
J7  TMS-102-01  [SIP2_50LS]
J8  TMS-103-01  [SIP3_50LS]
J9  Conn_DB9F  [NorComp_db9F_SMD]
J10  TMS-102-01  [SIP2_50LS]
L1  DA2304-AL  [DA2304]
R152  100K  [SM-7351-RES-0402]
R153  100K  [SM-7351-RES-0402]
R174  2.2K  [sm-7351-res-0402]
R175  0  [SM-7351-RES-0402]
R181  33  [SM-7351-RES-0402]
R186  33  [SM-7351-RES-0402]
R238  120  [SM-7351-RES-0402]
U16  ISO1050  [so8_w_dub]
U27  TPS76650  [soic_8]
U28  ISO1176T  [u_16_dw]
sheet P10_PRU_CPSW_ETHERNET_MUX
C17  0.1uF  [SM-7351-CAP-0402]
C18  0.1uF  [SM-7351-CAP-0402]
C19  0.1uF  [SM-7351-CAP-0402]
C20  0.1uF  [SM-7351-CAP-0402]
C92  10uF  [SM-7351-CAP-0805]
C94  10uF  [SM-7351-CAP-0805]
R40  1K  [SM-7351-RES-0402]
R41  1K  [SM-7351-RES-0402]
R138  0  [SM-7351-RES-0402]
R139  0  [SM-7351-RES-0402]
R145  2.2K  [sm-7351-res-0402]
R146  0  [SM-7351-RES-0402]
R147  0  [SM-7351-RES-0402]
R148  2.2K  [sm-7351-res-0402]
R149  0  [SM-7351-RES-0402]
R150  0  [SM-7351-RES-0402]
U7  SN74LVC1G32DCK  [SC70-5-43M]
U8  SN74LVC1G32DCK  [SC70-5-43M]
U9  SN74CBTLV3257RGY  [QFN4X3P5-16-39M]
U11  SN74CBTLV3257RGY  [QFN4X3P5-16-39M]
sheet P11_Ethernet0
C2  0.01uF  [SM-7351-CAP-0402]
C5  0.01uF  [SM-7351-CAP-0402]
C6  0.1uF  [SM-7351-CAP-0402]
C10  0.01uF  [SM-7351-CAP-0402]
C11  0.01uF  [SM-7351-CAP-0402]
C12  0.01uF  [SM-7351-CAP-0402]
C16  0.1uF  [SM-7351-CAP-0402]
C21  0.1uF  [SM-7351-CAP-0402]
C22  0.1uF  [SM-7351-CAP-0402]
C71  0.1uF  [SM-7351-CAP-0402]
C72  0.1uF  [SM-7351-CAP-0402]
C77  0.1uF  [SM-7351-CAP-0402]
C78  0.1uF  [SM-7351-CAP-0402]
C81  10uF  [SM-7351-CAP-0805]
C82  0.1uF  [SM-7351-CAP-0402]
C89  18pF, 50V  [SM-7351-CAP-0402]
C90  18pF, 50V  [SM-7351-CAP-0402]
D4  LED Yellow  [LEDLTST-S220]
J2  RJ-45 10_100Mb  [CNRJ45-1X1WLED]
J18  HEADER 3  [header_3x1]
R8  2.2K  [sm-7351-res-0402]
R10  4.87K  [SM-7351-RES-0402]
R13  33  [SM-7351-RES-0402]
R16  2.2K  [sm-7351-res-0402]
R19  2.2K  [sm-7351-res-0402]
R21  10K  [SM-7351-RES-0402]
R30  2.2K  [sm-7351-res-0402]
R31  2.2K  [sm-7351-res-0402]
R32  2.2K  [sm-7351-res-0402]
R33  2.2K  [sm-7351-res-0402]
R34  2.2K  [sm-7351-res-0402]
R39  4.7K  [SM-7351-RES-0402]
R42  33  [SM-7351-RES-0402]
R89  330  [SM-7351-RES-0402]
R90  2.2K  [sm-7351-res-0402]
R91  0  [SM-7351-RES-0402]
R92  2.2K  [sm-7351-res-0402]
R93  330  [SM-7351-RES-0402]
R113  2.2K  [sm-7351-res-0402]
R114  2.2K  [sm-7351-res-0402]
R116  49.9  [SM-7351-RES-0402]
R117  49.9  [SM-7351-RES-0402]
R118  49.9  [SM-7351-RES-0402]
R119  49.9  [SM-7351-RES-0402]
R124  2.2K  [sm-7351-res-0402]
R130  330  [SM-7351-RES-0402]
R144  33  [SM-7351-RES-0402]
R154  33  [SM-7351-RES-0402]
R241  0  [SM-7351-RES-0603]
R242  0  [SM-7351-RES-0603]
R280  0  [SM-7351-RES-0603]
TP7  TP1mm  [tp_smd1mmcircle]
TP9  TP1mm  [tp_smd1mmcircle]
TP11  TP1mm  [tp_smd1mmcircle]
TP13  TP1mm  [tp_smd1mmcircle]
TP15  TP1mm  [tp_smd1mmcircle]
TP20  TP  [TH_TP_5002]
TP32  TP1mm  [tp_smd1mmcircle]
TP34  TP1mm  [tp_smd1mmcircle]
TP35  TP1mm  [tp_smd1mmcircle]
U3  TLK110  [HTQFP_48pin]
U5  SN74LVC1G08  [sm-so-sc70-5]
U12  CDCE913  [TSSOP5X4-14-47M]
Y1  25MHz  [SM_OSC_ABM3]
sheet P12_Ethernet1
C1  0.01uF  [SM-7351-CAP-0402]
C3  0.01uF  [SM-7351-CAP-0402]
C4  0.1uF  [SM-7351-CAP-0402]
C9  0.01uF  [SM-7351-CAP-0402]
C14  0.1uF  [SM-7351-CAP-0402]
C15  0.01uF  [SM-7351-CAP-0402]
C73  0.1uF  [SM-7351-CAP-0402]
C74  0.1uF  [SM-7351-CAP-0402]
C79  0.1uF  [SM-7351-CAP-0402]
C80  0.1uF  [SM-7351-CAP-0402]
C83  0.1uF  [SM-7351-CAP-0402]
C84  10uF  [SM-7351-CAP-0805]
D5  LED Yellow  [LEDLTST-S220]
J1  RJ-45 10_100Mb  [CNRJ45-1X1WLED]
J19  HEADER 3  [header_3x1]
R7  2.2K  [sm-7351-res-0402]
R9  4.87K  [SM-7351-RES-0402]
R12  33  [SM-7351-RES-0402]
R15  2.2K  [sm-7351-res-0402]
R18  2.2K  [sm-7351-res-0402]
R27  2.2K  [sm-7351-res-0402]
R28  2.2K  [sm-7351-res-0402]
R29  2.2K  [sm-7351-res-0402]
R94  330  [SM-7351-RES-0402]
R95  2.2K  [sm-7351-res-0402]
R96  0  [SM-7351-RES-0402]
R97  2.2K  [sm-7351-res-0402]
R98  330  [SM-7351-RES-0402]
R110  2.2K  [sm-7351-res-0402]
R112  2.2K  [sm-7351-res-0402]
R120  49.9  [SM-7351-RES-0402]
R121  49.9  [SM-7351-RES-0402]
R122  49.9  [SM-7351-RES-0402]
R123  49.9  [SM-7351-RES-0402]
R129  2.2K  [sm-7351-res-0402]
R131  330  [SM-7351-RES-0402]
R134  2.2K  [sm-7351-res-0402]
R135  2.2K  [sm-7351-res-0402]
R239  0  [SM-7351-RES-0603]
R240  0  [SM-7351-RES-0603]
R279  0  [SM-7351-RES-0603]
TP8  TP1mm  [tp_smd1mmcircle]
TP10  TP1mm  [tp_smd1mmcircle]
TP12  TP1mm  [tp_smd1mmcircle]
TP14  TP1mm  [tp_smd1mmcircle]
TP16  TP1mm  [tp_smd1mmcircle]
TP17  TP  [TH_TP_5002]
TP33  TP1mm  [tp_smd1mmcircle]
TP36  TP1mm  [tp_smd1mmcircle]
TP40  TP1mm  [tp_smd1mmcircle]
U2  TLK110  [HTQFP_48pin]
sheet P13_Host Expansion & MMC0 & LCD
A1  OSD-9616  [-]
C60  2.2uF  [SM-7351-CAP-0805]
C62  2.2uF  [SM-7351-CAP-0805]
C63  2.2uF  [SM-7351-CAP-0805]
C68  0.01uF  [SM-7351-CAP-0402]
C69  0.01uF  [SM-7351-CAP-0402]
C70  0.1uF  [SM-7351-CAP-0402]
C252  1uF  [SM-7351-CAP-0603]
C255  10pF  [SM-7351-CAP-0402]
C258  2.2uF  [SM-7351-CAP-0805]
C260  10uF  [SM-7351-CAP-0805]
C265  0.1uF  [SM-7351-CAP-0402]
C266  1uF  [SM-7351-CAP-0402]
C267  0.022uF  [SM-7351-CAP-0402]
C268  1uF  [SM-7351-CAP-0402]
C269  0.1uF  [SM-7351-CAP-0402]
C270  1uF  [SM-7351-CAP-0402]
C271  1uF  [SM-7351-CAP-0402]
C272  0.1uF  [SM-7351-CAP-0402]
D20  MBR0520LT1  [mbr0520L]
J3  Header 9x2 Female  [HDR2X9VER_335M]
J4  Header 15x2 Female  [HDR2X15-344M]
J16  SCHA5B0200  [SD-MICRO-SCHA5B0300]
J17  10051922-1410ELF  [CON14_P5MM_3P75X9P5SMD]
L2  2.2uH  [IND108SMD_110X102]
R87  1K  [SM-7351-RES-0402]
R88  1K  [SM-7351-RES-0402]
R99  1K  [SM-7351-RES-0402]
R100  1K  [SM-7351-RES-0402]
R220  1.62M  [SM-7351-RES-0402]
R221  180K  [SM-7351-RES-0402]
R224  0  [SM-7351-RES-0402]
R225  0  [SM-7351-RES-0402]
R230  0  [SM-7351-RES-0402]
R231  10K  [SM-7351-RES-0402]
R232  392K  [SM-7351-RES-0402]
R233  10K  [SM-7351-RES-0402]
R234  10K  [SM-7351-RES-0402]
R235  10K  [SM-7351-RES-0402]
R236  10K  [SM-7351-RES-0402]
R237  10K  [SM-7351-RES-0402]
SW1  Rotary Switch  [SW-ND3FR10]
U24  TPD6E001  [U_10_RSE]
U25  PCA9536DGK  [MSOP3X3-8-43M]
U34  TPS61041  [DBV5]

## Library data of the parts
C23 C27-C29 C38 C39 C47 C81 C84 C92 C94 C95 C101 C102 C104 C107 C121 C154 C178 C179 C205 C209 C210 C212 C215 C260 = 10uFCapacitor16V10%0805
C25 C26 C30 C31 C103 C105 C115 C117 C118 C122 C126-C129 C133 C136 C138 C140 C141 C144 C146 C147 C153 C156 C158 C161 C165 C168 C174 C176 C180 C183 = 0.1uFCapacitor6.3V10%0201
C1-C3 C5 C9-C12 C15 C36 C37 C68 C69 C98 C106 C108-C114 C116 C119 C120 C123 C124 C130-C132 C134 C135 C137 C139 C142 C143 C149-C152 C155 C157 C160 C163 C164 C166 C169-C173 C175 C177 C181 C182 C187 C189 C190 C192 C193 C196 C197 C201-C204 C229 = 0.01uFCapacitor16V10%0402
C76 C195 C198-C200 C266 C268 C270 C271 = 1uFCapacitor10V10%0402
FB2 FB3 FB11 = FerBead_180ohm200mA
R21 R65 R101 R111 R125 R231 R233-R237 = 10KOhmResistor1_16W0402
R212 R219 = 0.05ohm0.5W1%Sense1206
TP24 TP25 = TESTPT1
U14 = AM335X_15mmx15mm: MfrNum: AM3359ZCZ
C4 C6 C7 C14 C16-C20 C32 C41 C70-C75 C77-C80 C82 C83 C85-C88 C96 C162 C167 C185 C188 C214 C265 C269 C272 = 0.1uFCapacitor16V10%0402
C45 C186 = 4.7uFCapacitor16V10%0603
C275 C277 = 1C_0.01uFCapacitor16V10%0402
D1 D2 = LED_Tricolor_RedGreenYellow
D3 = LED_Green
J5 J8 = Header_1.27mm_3pin
Q1-Q4 = NPN_DMC564040R
R1-R6 R89 R93 R94 R98 R128 R130 R131 = 330ohm1_16W5%smd0402
R11 R62 R63 R178 R184 R191 R195 = 10KOhmResistor1_10W1%0402
R37 R44 R45 R50 R54 R55 = 1R_10KOhmResistor1_10W1%0402
R38 R43 R46-R49 R51-R53 R56 R57 R152 R153 R157-R171 = 100KOhmResistor1_16W0402
R40 R41 R59 R87 R88 R99 R100 R103 R104 R106-R109 R127 = 1KOhmResistor1_16W0402
R91 R96 R105 R126 R138 R139 R146 R147 R149 R150 R175 R224 R225 R230 = ZeroOhmResistor1_16W0402
R39 R277 R278 = 1R_4.7KOhmResistor1_16W0402
TP7-TP16 TP21 TP22 TP32-TP37 TP40 = Testpoint_SMD1mmCircle
U4 = SN74CB3Q3306APW
U37 U38 = 1A_SN74LV244APWRG3
C216 = 0.001uFCapacitor50V5%0402
R12 R13 R179-R182 R186 = 33ohmResistor1_16W5%0402
R183 = 240OhmResistor1_10W1%0402
RP1-RP3 = 33ohmx8_1_16W5%smd
U15 = MT41J128M16JT-125
U29 = TPS51200
U1 = M29W160G
U26 = SN74ALVCH16374DGVR
C24 C191 = 4.7uFCapacitor16V20%Tant
C145 C184 = 100pFCapacitor16V10%0402
D11 D13 D20 = Diode_500mA20V
J6 J7 J10 = Header_1.27mm_2pin
J9 = Conn_DSUB9F
L1 = DA2304-ALB
R7 R8 R15 R16 R27-R34 R90 R92 R95 R97 R110 R112-R114 R124 R129 R134 R135 R174 = 2.2KOhmResistor1_16W0402
R238 = 1R_120ohm1_16W1%smd0402
U16 = ISO1050
U27 = TPS76650
U28 = ISO1176T
R18 R19 R145 R148 = 1R_2.2KOhmResistor1_16W0402
U7 U8 = SN74LVC1G32DCK
U9 U11 = SN74CBTLV3257RGY
C21 C22 = 1C_0.1uFCapacitor16V10%0402
C89 C90 = 1C_18pFCapacitor50V5%0402
D4 D5 = LED_Yellow
J1 J2 = 2J_ConnectorRJ45_10_100MbAMDIX
J18 J19 = 2H_Header_3x1
R9 R10 = 1R_4.87KOhmResistor1_16W0402
R42 R144 R154 = 1R_33ohmResistor1_16W5%0402
R116-R123 = 49.9OhmResistor1_16W0402
R239-R242 R279 R280 = 1R_ZeroOhmResistor1_16W0603
TP17 TP20 = TestPointThroughHole
U2 U3 = TLK110
U5 = SN74LVC1G08DCKT_SC70
U12 = 1A_CDCE913
Y1 = Crystal25MHzABM3
A1 = LCD_OSD9616P0899-10
C60 C258 = 2.2uF16V10%SMD0805
C62 C63 = 2.2uFCapacitor35V20%smd0805
C252 = 1uFCapacitor50V10%0603
C255 = 10pFCapacitor50V1%smd0402
C267 = 0.022uFCapacitor16VX7Rsmd0402
J3 = Header9x2_0.1in_Female
J4 = Header15x2_0.1in_Female
J16 = Conn_microSD_8
J17 = Conn_14pin_0.5mm_FPC
L2 = 2.2uHInductor20%1Asmd
R220 = 1.62MOhmResistor1_16W0402
R221 = 180KOhmResistor1_16W0402
R232 = 392KOhmResistor1_10W1%0402
SW1 = SwitchDIPRotaries_smd
U24 = TPD6E001RSE
U25 = PCA9536
U34 = TPS61041DBV

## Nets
AGND_CAN: J9.10 J9.11 R175.1(P1)
AGND_PRUETH0: C2.2 C5.2 R242.1(P1) U3.15(AGND) U3.19(AGND)
AGND_PRUETH1: C1.2 C3.2 R239.1(P1) U2.15(AGND) U2.19(AGND)
AGNDFRAME_PRUETH0: J2.13(SHLD1) J2.14(SHLD2) R91.1(P1)
AGNDFRAME_PRUETH1: J1.13(SHLD1) J1.14(SHLD2) R96.1(P1)
DGND: C4.2 C6.2 C7.2 C9.2 C10.2 C11.2 C12.2 C14.2 C15.2 C16.2 C17.2 C18.2 C19.2 C20.2 C21.2 C22.2 C23.2 C25.2 C26.2 C27.2 C28.2 C29.2 C30.2 C31.2 C32.2 C37.2 C38.2 C39.2 C41.2 C45.2 C47.2 C60.2 C62.2 C63.2 C68.2 C69.2 C70.2 C71.2 C72.2 C73.2 C74.2 C75.2 C76.2 C77.2 C78.2 C79.2 C80.2 C81.2 C82.2 C83.2 C84.2 C85.2 C86.2 C87.2 C88.2 C89.1 C90.1 C92.2 C94.2 C101.2 C102.2 C103.2 C104.2 C105.2 C108.2 C109.1 C110.1 C111.1 C112.2 C113.2 C114.2 C115.2 C116.2 C117.2 C118.2 C119.1 C120.2 C121.1 C122.2 C123.2 C124.2 C126.2 C127.2 C128.2 C129.2 C130.2 C131.2 C132.2 C133.2 C134.2 C135.2 C136.2 C137.1 C138.2 C139.2 C140.2 C141.2 C142.2 C143.1 C144.2 C145.2 C146.2 C147.2 C149.2 C150.2 C151.2 C152.2 C153.2 C154.2 C155.2 C156.2 C157.1 C158.2 C160.1 C161.2 C163.2 C164.2 C165.2 C166.2 C167.2 C168.2 C169.2 C170.2 C171.2 C172.1 C173.1 C174.2 C175.1 C176.2 C177.2 C178.2 C179.1 C180.2 C181.2 C182.2 C183.2 C184.2 C186.2 C187.2 C188.2 C189.2 C190.2 C192.2 C193.2 C195.2 C196.2 C197.2 C198.2 C199.2 C200.2 C201.2 C202.1 C203.2 C204.2 C205.2 C209.2 C210.2 C212.2 C214.2 C215.2 C216.2 C229.1 C252.2 C258.2 C260.2 C265.2 C266.2 C267.2 C268.2 C269.2 C272.2 C275.2 C277.2 FB11.2 J1.8 J2.8 J3.2 J3.15 J16.6(VSS) J16.9(GND) J17.8 Q1.1(4) Q1.4 Q2.1(4) Q2.4 Q3.1(4) Q3.4 Q4.1(4) R9.1(P1) R10.1(P1) R38.1(P1) R40.1(P1) R41.1(P1) R62.1 R65.2(P2) R87.1(P1) R88.1(P1) R91.2(P2) R96.2(P2) R99.1(P1) R100.1(P1) R103.1(P1) R104.1(P1) R106.1(P1) R107.1(P1) R108.1(P1) R109.1(P1) R110.1(P1) R113.1(P1) R127.1(P1) R157.1(P1) R158.1(P1) R159.1(P1) R160.1(P1) R161.1(P1) R162.1(P1) R163.1(P1) R164.1(P1) R165.1(P1) R166.1(P1) R167.1(P1) R168.1(P1) R169.1(P1) R170.1(P1) R171.1(P1) R174.1(P1) R178.1 R183.1 R195.1 R221.1(P1) R232.2 R239.2(P2) R242.2(P2) R277.1(P1) R278.1(P1) U1.H1(VSS1) U1.H6(VSS2) U2.35(IOGND) U2.36(DGND) U2.47(IOGND) U2.49(GNDPAD) U3.35(IOGND) U3.36(DGND) U3.47(IOGND) U3.49(GNDPAD) U4.4(GND) U5.3(GND) U7.3(GND) U8.3(GND) U9.8(GND) U9.13(4B2) U9.14(4B1) U9.17(EPAD) U11.8(GND) U11.17(EPAD) U12.5(GND1) U12.10(GND2) U14.A1(VSS) U14.A18(VSS) U14.F8(VSS) U14.G8(VSS) U14.G9(VSS) U14.G11(VSS) U14.G12(VSS) U14.H6(VSS) U14.H7(VSS) U14.H8(VSS) U14.H9(VSS) U14.H10(VSS) U14.H12(VSS) U14.J6(VSS) U14.J7(VSS) U14.J8(VSS) U14.J9(VSS) U14.J10(VSS) U14.J11(VSS) U14.K7(VSS) U14.K9(VSS) U14.K10(VSS) U14.K11(VSS) U14.L10(VSS) U14.L11(VSS) U14.L12(VSS) U14.L13(VSS) U14.M6(VSS) U14.M7(VSS) U14.M8(VSS) U14.M9(VSS) U14.M10(VSS) U14.M12(VSS) U14.M14(VSSA_USB) U14.N7(VSS) U14.N10(VSS) U14.N11(VSS) U14.N14(VSSA_USB) U14.V1(VSS) U14.V18(VSS) U15.A9(VSS1) U15.B1(VSSQ1) U15.B3(VSS2) U15.B9(VSSQ2) U15.D1(VSSQ3) U15.D8(VSSQ4) U15.E1(VSS3) U15.E2(VSSQ5) U15.E8(VSSQ6) U15.F9(VSSQ7) U15.G1(VSSQ8) U15.G8(VSS4) U15.G9(VSSQ9) U15.J2(VSS5) U15.J8(VSS6) U15.M1(VSS7) U15.M9(VSS8) U15.P1(VSS9) U15.P9(VSS10) U15.T1(VSS11) U15.T9(VSS12) U16.4(GND1) U24.5(GND) U25.4(GND) U26.1(1~{OE}) U26.4(GND1) U26.10(GND2) U26.15(GND3) U26.21(GND4) U26.24(2~{OE}) U26.28(GND5) U26.34(GND6) U26.39(GND7) U26.45(GND8) U28.3(GND1) U29.4(PGND) U29.8(GND) U29.11(PWRPD) U34.2(GND) U37.10(GND) U38.10(GND) ; also on sheet 10 11 12 14 15
GND_EARTH: J16.11(GND3) J16.12(GND4) J16.13(GND5) J16.14(GND6) J16.15(GND7) J16.16(GND8) ; also on sheet 11 14
GND_OSC0: C106.2 ; also on sheet 11
GNDA_ADC: C36.2 FB11.1 U14.E8(VSSA_ADC) ; also on sheet 10 15
GNDPROFI: C24.2(NEG) C95.2 C96.2 C98.2 C107.2 C185.2 C191.2(NEG) J7.2 J8.3 L1.6 L1.7 R153.1(P1) R175.2(P2) U16.5(GND2) U27.3(GND) U27.4(~{EN}) U28.9(GND2) U28.11(GND2) U28.14(GND2) U28.15(GND2)
V3_3D: C7.1 C9.1 C10.1 C11.1 C12.1 C15.1 C17.1 C18.1 C19.1 C20.1 C22.1 C69.1 C70.1 C75.1 C76.1 C77.1 C78.1 C79.1 C80.1 C85.1 C86.1 C87.1 C88.1 C92.1 C94.1 C123.1 C190.1 C265.1 C266.1 C275.1 C277.1 J3.1 J17.7 L1.2 L1.3 R11.1 R15.2(P2) R16.2(P2) R18.2(P2) R19.2(P2) R21.2(P2) R27.2(P2) R28.2(P2) R29.2(P2) R30.2(P2) R31.2(P2) R32.2(P2) R33.2(P2) R34.2(P2) R89.2(P2) R90.2(P2) R92.2(P2) R93.2(P2) R94.2(P2) R95.2(P2) R97.2(P2) R98.2(P2) R101.2(P2) R111.2(P2) R112.1(P1) R114.1(P1) R116.1(P1) R117.1(P1) R118.1(P1) R119.1(P1) R120.1(P1) R121.1(P1) R122.1(P1) R123.1(P1) R124.2(P2) R125.2(P2) R129.2(P2) R130.2(P2) R131.2(P2) R134.2(P2) R135.2(P2) R145.2(P2) R148.2(P2) R240.2(P2) R241.2(P2) R279.1(P1) R280.1(P1) SW1.C1 SW1.C2 U1.G4(VCC) U2.32(VDD33_IO) U2.48(VDD33_IO) U3.32(VDD33_IO) U3.48(VDD33_IO) U4.8(VCC) U5.5(VCC) U7.5(VCC) U8.5(VCC) U9.16(VCC) U11.16(VCC) U12.6(VDDOUT1) U12.7(VDDOUT2) U16.1(VCC1) U25.8(VCC) U26.7(VCC1) U26.18(VCC2) U26.31(VCC3) U26.42(VCC4) U28.4(VCC1) U37.20(VCC) U38.20(VCC) ; also on sheet 10 12 14 15
V3_3D_PROFIA: L1.4 U28.1(D1)
V3_3D_PROFIB: L1.1 U28.2(D2)
V3_3D_PRUETH0JCK: C71.1 C72.1 J2.3 J2.4 R280.2(P2)
V3_3D_PRUETH1JCK: C73.1 C74.1 J1.3 J1.4 R279.2(P2)
V5_0D: C60.1 FB3.2 L2.1 R224.1(P1) U34.5(VIN) ; also on sheet 12 15
V13: C62.1 C252.1 C255.1 C258.1 D20.1(CATHODE) J17.1 R220.2(P2)
V24_IN: J3.17 ; also on sheet 12
VBAT_LCD: C268.1 C269.1 J17.10
VDD1_SMPS: R219.1(I1) ; also on sheet 12
VDD1_SMPS_AM335X: C37.1 C151.1 C170.1 C203.1 C204.1 C210.1 R219.2(I2) TP25.1(TP) U14.A2(VDD_MPU_MON) U14.F10(VDD_MPU) U14.F11(VDD_MPU) U14.F12(VDD_MPU) U14.F13(VDD_MPU) U14.G13(VDD_MPU) U14.H13(VDD_MPU) U14.J13(VDD_MPU)
VDD2_SMPS: R212.1(I1) ; also on sheet 12
VDD2_SMPS_AM335X: C130.1 C131.1 C134.1 C142.1 C149.1 C150.1 C154.1 C155.1 C163.1 C164.1 C169.1 C171.1 C178.1 C187.1 C192.1 R212.2(I2) U14.F6(VDD_CORE) U14.F7(VDD_CORE) U14.G6(VDD_CORE) U14.G7(VDD_CORE) U14.G10(VDD_CORE) U14.H11(VDD_CORE) U14.J12(VDD_CORE) U14.K6(VDD_CORE) U14.K8(VDD_CORE) U14.K12(VDD_CORE) U14.L6(VDD_CORE) U14.L7(VDD_CORE) U14.L8(VDD_CORE) U14.L9(VDD_CORE) U14.M11(VDD_CORE) U14.M13(VDD_CORE) U14.N8(VDD_CORE) U14.N9(VDD_CORE) U14.N12(VDD_CORE) U14.N13(VDD_CORE)
VDD_LED: C45.1 D1.1(A) D2.1(A) FB3.1 R128.2(P2)
VDD_RTC: C195.1 U14.D6(CAP_VDD_RTC)
VDDA_ADC: C36.1 FB2.1 U14.D8(VDDA_ADC) ; also on sheet 10
VDDS_DDR: C25.1 C26.1 C27.1 C28.1 C30.1 C31.1 C101.1 C102.1 C103.1 C104.1 C105.1 C115.1 C117.1 C118.1 C122.1 C126.1 C127.1 C128.1 C129.1 C133.1 C136.1 C138.1 C140.1 C141.1 C144.1 C146.1 C147.1 C153.1 C156.1 C158.1 C161.1 C162.2 C165.1 C168.1 C174.1 C176.1 C180.1 C183.1 C209.1 R59.1(P1) R191.2 U14.E5(VDDS_DDR) U14.F5(VDDS_DDR) U14.G5(VDDS_DDR) U14.H5(VDDS_DDR) U14.J5(VDDS_DDR) U14.K5(VDDS_DDR) U14.L5(VDDS_DDR) U15.A1(VDDQ1) U15.A8(VDDQ2) U15.B2(VDD1) U15.C1(VDDQ3) U15.C9(VDDQ4) U15.D2(VDDQ5) U15.D9(VDD9) U15.E9(VDDQ7) U15.F1(VDDQ8) U15.G7(VDD2) U15.H2(VDDQ9) U15.H9(VDDQ10) U15.K2(VDD4) U15.K8(VDD5) U15.N1(VDD6) U15.N9(VDD7) U15.R1(VDD8) U15.R9(VDD3) U29.2(VLDOIN) ; also on sheet 12
AM335X_OSC0_IN: R144.2 ; also on sheet 11
AM335X_REFCLK_RMII1: R13.2 ; also on sheet 10
AM335X_REFCLK_RMII2: R12.2 ; also on sheet 10
B_PRUETH0_LINKLED: J2.10(D2) R90.1(P1) TP20.1 U3.28(LED_LINK)
C1N: C270.2 J17.11
C1P: C270.1 J17.12
C2N: C271.2 J17.13
C2P: C271.1 J17.14
CAN0_H: J9.7 R238.1(P1) U16.7(CANH)
CAN0_L: J9.2 R238.2(P2) U16.6(CANL)
CAN0_RXDF: R186.2 U16.2(RXD)
CAN0_TXDF: C145.1 R181.2 U16.3(TXD)
CAN_GND/PROFIBUS_A: J8.2 J9.3
CAP_VBB_MPU: C199.1 U14.C10(CAP_VBB_MPU)
CAP_VDD_SRAM_CORE: C198.1 U14.D9(CAP_VDD_SRAM_CORE)
CAP_VDD_SRAM_MPU: C200.1 U14.D11(CAP_VDD_SRAM_MPU)
DDR_A0: RP2.1 U15.N3(A0) ; also on sheet 11
DDR_A1: RP2.3 U15.P7(A1) ; also on sheet 11
DDR_A2: RP3.7 U15.P3(A2) ; also on sheet 11
DDR_A3: RP3.4 U15.N2(A3) ; also on sheet 11
DDR_A4: RP2.6 U15.P8(A4) ; also on sheet 11
DDR_A5: RP3.6 U15.P2(A5) ; also on sheet 11
DDR_A6: RP1.2 U15.R8(A6) ; also on sheet 11
DDR_A7: RP1.8 U15.R2(A7) ; also on sheet 11
DDR_A8: RP1.1 U15.T8(A8) ; also on sheet 11
DDR_A9: RP1.6 U15.R3(A9) ; also on sheet 11
DDR_A10: RP1.5 U15.L7(A10) ; also on sheet 11
DDR_A11: RP1.4 U15.R7(A11) ; also on sheet 11
DDR_A12: RP2.4 U15.N7(A12) ; also on sheet 11
DDR_A13: RP1.7 U15.T3(A13) ; also on sheet 11
DDR_A14: RP1.3 U15.T7(A14) ; also on sheet 11
DDR_BA0: RP3.3 U15.M2(BA0) ; also on sheet 11
DDR_BA1: RP2.5 U15.N8(BA1) ; also on sheet 11
DDR_BA2: RP3.8 U15.M3(BA2) ; also on sheet 11
DDR_CASn: RP3.5 U15.K3(CASn) ; also on sheet 11
DDR_CKE: R178.2 U15.K9(CKE) ; also on sheet 11
DDR_CLK: R179.1 U15.J7(CK) ; also on sheet 11
DDR_CLKn: R182.1 U15.K7(CKn) ; also on sheet 11
DDR_CSn: RP3.1 U15.L2(CSn) ; also on sheet 11
DDR_D0: U15.H7(DQ7) ; also on sheet 11
DDR_D1: U15.F8(DQ3) ; also on sheet 11
DDR_D2: U15.G2(DQ6) ; also on sheet 11
DDR_D3: U15.F2(DQ2) ; also on sheet 11
DDR_D4: U15.H3(DQ4) ; also on sheet 11
DDR_D5: U15.H8(DQ5) ; also on sheet 11
DDR_D6: U15.E3(DQ0) ; also on sheet 11
DDR_D7: U15.F7(DQ1) ; also on sheet 11
DDR_D8: U15.C3(DQ9) ; also on sheet 11
DDR_D9: U15.C2(DQ11) ; also on sheet 11
DDR_D10: U15.D7(DQ8) ; also on sheet 11
DDR_D11: U15.C8(DQ10) ; also on sheet 11
DDR_D12: U15.A3(DQ15) ; also on sheet 11
DDR_D13: U15.A2(DQ13) ; also on sheet 11
DDR_D14: U15.A7(DQ12) ; also on sheet 11
DDR_D15: U15.B8(DQ14) ; also on sheet 11
DDR_DQM0: U15.E7(LDM) ; also on sheet 11
DDR_DQM1: U15.D3(UDM) ; also on sheet 11
DDR_DQS0: U15.F3(LDQS) ; also on sheet 11
DDR_DQS1: U15.C7(UDQS) ; also on sheet 11
DDR_DQSN0: U15.G3(LDQSn) ; also on sheet 11
DDR_DQSN1: U15.B7(UDQSn) ; also on sheet 11
DDR_ODT: RP3.2 U15.K1(ODT) ; also on sheet 11
DDR_RASn: R180.1 U15.J3(RASn) ; also on sheet 11
DDR_RESETN: R59.2(P2) U15.T2(RESET#) ; also on sheet 11
DDR_VREF: C167.1 C188.1 TP21.1 U15.H1(VREF_DQ) U15.M8(VREF_CA) U29.6(REFOUT) ; also on sheet 11
DDR_VTT_EN: R62.2 R63.1 U29.7(EN) ; also on sheet 10
DDR_WEn: RP2.2 U15.L3(WEn) ; also on sheet 11
EMU2_GPIO0_19: Q2.2(5) R106.2(P2) ; also on sheet 11 14
EMU3_GPIO0_20: Q3.5 R108.2(P2) ; also on sheet 11 14
EMU4: J3.10 ; also on sheet 10 14
ENZ_KALDO_1P8V: R65.1(P1) U14.B4(RTC_KALDO_ENn)
ETH0_CLKIN: R42.2 U3.34(XI)
ETH1_CLKIN: R154.2 U2.34(XI)
FET_nOE: R11.2 U4.1(nOE1) U4.7(nOE2) ; also on sheet 10
GPIO2-5: R21.1(P1) U5.1(A) ; also on sheet 11
GPIO2_12: U1.C3(A18) U37.5(2Y3) ; also on sheet 10
GPIO2_13: U1.D4(A19) U37.3(2Y4) ; also on sheet 10
GPIO3_18: J3.9 ; also on sheet 10 15
GPIO3_19: J3.11 U28.7(DE) ; also on sheet 10
GPIO3_20: J3.13 ; also on sheet 10
GPMC_A0: J4.1 U1.E1(A0) U26.2(1Q1)
GPMC_A1: J4.3 U1.D1(A1) U26.3(1Q2)
GPMC_A2: J4.5 U1.C1(A2) U26.5(1Q3)
GPMC_A3: J4.7 U1.A1(A3) U26.6(1Q4)
GPMC_A4: J4.9 U1.B1(A4) U26.8(1Q5)
GPMC_A5: J4.11 U1.D2(A5) U26.9(1Q6)
GPMC_A6: J4.13 U1.C2(A6) U26.11(1Q7)
GPMC_A7: J4.15 U1.A2(A7) U26.12(1Q8)
GPMC_A8: J4.17 U1.B5(A8) U26.13(2Q1)
GPMC_A9: J4.19 U1.A5(A9) U26.14(2Q2)
GPMC_A10: U1.C5(A10) U26.16(2Q3)
GPMC_A11: U1.D5(A11) U26.17(2Q4)
GPMC_A12: U1.B6(A12) U26.19(2Q5)
GPMC_A13: U1.A6(A13) U26.20(2Q6)
GPMC_A14: U1.C6(A14) U26.22(2Q7)
GPMC_A15: U1.D6(A15) U26.23(2Q8)
GPMC_AD0: J4.2 U1.E2(DQ0) U26.47(1D1) ; also on sheet 11
GPMC_AD1: J4.4 U1.H2(DQ1) U26.46(1D2) ; also on sheet 11
GPMC_AD2: J4.6 U1.E3(DQ2) U26.44(1D3) ; also on sheet 11
GPMC_AD3: J4.8 U1.H3(DQ3) U26.43(1D4) ; also on sheet 11
GPMC_AD4: J4.10 U1.H4(DQ4) U26.41(1D5) ; also on sheet 11
GPMC_AD5: J4.12 U1.E4(DQ5) U26.40(1D6) ; also on sheet 11
GPMC_AD6: J4.14 U1.H5(DQ6) U26.38(1D7) ; also on sheet 11
GPMC_AD7: J4.16 U1.E5(DQ7) U26.37(1D8) ; also on sheet 11
GPMC_AD8: J4.18 U1.F2(DQ8) U26.36(2D1) ; also on sheet 11
GPMC_AD9: J4.20 U1.G2(DQ9) U26.35(2D2) ; also on sheet 11
GPMC_AD10: J4.22 U1.F3(DQ10) U26.33(2D3) ; also on sheet 11
GPMC_AD11: J4.24 U1.G3(DQ11) U26.32(2D4) ; also on sheet 11
GPMC_AD12: J4.26 U1.F4(DQ12) U26.30(2D5) ; also on sheet 11
GPMC_AD13: J4.28 U1.G5(DQ13) U26.29(2D6) ; also on sheet 11
GPMC_AD14: J4.30 U1.F5(DQ14) U26.27(2D7) ; also on sheet 11
GPMC_AD15: J4.29 U1.G6(DQ15_A-1) U26.26(2D8) ; also on sheet 11
GPMC_ADVn_ALE: J4.27 U26.25(2CLK) U26.48(1CLK) ; also on sheet 11
GPMC_CSn0: R125.1(P1) U1.F1(~{E}) ; also on sheet 11
GPMC_CSn2: J4.21 ; also on sheet 11
GPMC_NOR_A1: U1.E6(A16) ; also on sheet 10
GPMC_NOR_A2: U1.B2(A17) ; also on sheet 10
GPMC_OEn_REn: J4.25 U1.G1(~{G}) ; also on sheet 11
GPMC_WEn: J4.23 U1.A4(~{W}) ; also on sheet 11
I2C0_SCL: J3.6 J17.5 U12.12(S2/SCL) U25.6(SCL) ; also on sheet 10 12 15
I2C0_SDA: J3.4 J17.4 U12.13(S1/SDA) U25.7(SDA) ; also on sheet 10 12 15
IREF: J17.3 R232.1
LATCH0_IN: J3.3 ; also on sheet 10
LATCH1_IN: J3.5 ; also on sheet 10
LCD_BST_CONV_CTL: R225.2(P2) ; also on sheet 10
LED_1: Q2.5 R107.2(P2) ; also on sheet 10
LED_2: Q1.2(5) R104.2(P2) R126.2(P2) ; also on sheet 10
LED_3: Q1.5 R103.2(P2) ; also on sheet 10
LED_4: Q3.2(5) R109.2(P2) TP37.1 ; also on sheet 11
MDIO_CLK: R149.2(P2) ; also on sheet 10
MDIO_DATA: R147.2(P2) ; also on sheet 10
MMC0_CLK: J16.5(CLOCK) R237.1(P1) U24.6(IO4) ; also on sheet 11
MMC0_CMD: J16.3(CMD) R235.1(P1) U24.3(IO3) ; also on sheet 11
MMC0_DAT0: J16.7(DAT0) R236.1(P1) U24.7(IO5) ; also on sheet 11
MMC0_DAT1: J16.8(DAT1) R234.1(P1) U24.8(IO6) ; also on sheet 11
MMC0_DAT2: J16.1(DAT2) R231.1(P1) U24.1(IO1) ; also on sheet 11
MMC0_DAT3: J16.2(CD/DAT3) R233.1(P1) U24.2(IO2) ; also on sheet 11
MUX_MII_CTL1: U9.1(S) U11.1(S) ; also on sheet 10
NOR_READY: R111.1(P1) U1.A3(R~{B})
NOR_RP: R105.2(P2) U1.B4(~{RP})
PGOOD_VTT: R184.1 TP22.1 U29.9(PGOOD)
PR1_MDIO_DATA: R146.2(P2) ; also on sheet 11
PR1_MDIO_MDCLK: R150.2(P2) ; also on sheet 11
PR1_MII0_RXLINK_SPEED: U4.2(1A) U38.9(2Y1) ; also on sheet 10
PR1_MII1_CLK: U2.38(MII_RX_CLK) ; also on sheet 11
PR1_MII1_COL_RMII2_CRS_DV: U9.9(3A) ; also on sheet 11
PR1_MII1_CRS: U2.40(MII_CRS) U9.10(3B2) ; also on sheet 10
PR1_MII1_RXD0: R135.1(P1) U2.43(MII_RXD_0) U11.10(3B2) ; also on sheet 11
PR1_MII1_RXD1: R28.1(P1) U2.44(MII_RXD_1) U9.6(2B2) ; also on sheet 11
PR1_MII1_RXD2: R134.1(P1) U2.45(MII_RXD_2) ; also on sheet 11
PR1_MII1_RXD3_RMII2_TXD0: U11.12(4A) ; also on sheet 11
PR1_MII1_RXDV_RMII2_RXD1: U9.7(2A) ; also on sheet 11
PR1_MII1_RXER_RMII2_RXD0: U11.9(3A) ; also on sheet 11
PR1_MII1_TXCLK_RMII2_TXEN: U11.4(1A) ; also on sheet 11
PR1_MII1_TXD0_RMII2_TXD1: U9.4(1A) ; also on sheet 11
PR1_MII1_TXD1: U2.4(MII_TXD_1) U9.3(1B2) ; also on sheet 11
PR1_MII1_TXD2: U2.5(MII_TXD_2) ; also on sheet 11
PR1_MII1_TXD3: U2.6(MII_TXD_3) ; also on sheet 11
PR1_MII1_TXEN_RMII2_RXERR: U11.7(2A) ; also on sheet 11
PR1_MII_CTL: R277.2(P2) R278.2(P2) U37.1(1OE#) U37.19(2OE#) U38.1(1OE#) U38.19(2OE#) ; also on sheet 10
PROFI_GND: J7.1 J9.5
PROFIBUS_A: J8.1 R152.1(P1) U28.12(A)
PROFIBUS_B: J9.8 R153.2(P2) U28.13(B)
PRUETH0_ACTLED: J2.12(D4) R92.1(P1) U3.26(LED_ACT)
PRUETH0_COL: R30.1(P1) U3.42(MII_COL) U8.1(A)
PRUETH0_CRS: U3.40(MII_CRS) ; also on sheet 10
PRUETH0_INT: R19.1(P1) U3.7(PWRDNn/INTn)
PRUETH0_JTCK: TP15.1 U3.8(JTAG_TCK)
PRUETH0_JTDI: TP7.1 U3.12(JTAG_TDI)
PRUETH0_JTDO: TP13.1 U3.9(JTAG_TDO)
PRUETH0_JTMS: TP11.1 U3.10(JTAG_TMS)
PRUETH0_JTRSTn: TP9.1 U3.11(JTAG_TRSTn)
PRUETH0_RESETn: U2.29(RESET_N) U3.29(RESET_N) U5.4(Y)
PRUETH0_RXCLK: U3.38(MII_RX_CLK) U38.5(2Y3) ; also on sheet 10
PRUETH0_RXD0: R31.1(P1) U3.43(MII_RXD_0) U38.12(1Y4) ; also on sheet 10
PRUETH0_RXD1: R32.1(P1) U3.44(MII_RXD_1) U38.14(1Y3) ; also on sheet 10
PRUETH0_RXD2: R33.1(P1) U3.45(MII_RXD_2) U38.16(1Y2) ; also on sheet 10
PRUETH0_RXD3: R34.1(P1) U3.46(MII_RXD_3) U38.18(1Y1) ; also on sheet 10
PRUETH0_RXDV: J18.2 TP35.1 U3.39(MII_RX_DV) U38.3(2Y4) ; also on sheet 10
PRUETH0_RXERR: R139.2(P2) U3.41(MII_RX_ERR) U8.2(B) ; also on sheet 10
PRUETH0_RXERR_COL: R139.1(P1) U4.6(2B) U8.4(Y)
PRUETH0_RXERR_COL_PROC: U4.5(2A) U38.7(2Y2) ; also on sheet 10
PRUETH0_SPEEDLED: D4.1(Cathode) R16.1(P1) TP34.1 U3.27(LED_SPEED) U4.3(1B)
PRUETH0_SWSTRAP: R124.1(P1) U3.21(SW_STRAPN)
PRUETH0_TXCLK: U3.1(MII_TX_CLK) U37.18(1Y1) ; also on sheet 10
PRUETH0_TXD0: U3.3(MII_TXD_0) U37.7(2Y2) ; also on sheet 10
PRUETH0_TXD1: U3.4(MII_TXD_1) U37.9(2Y1) ; also on sheet 10
PRUETH0_TXD2: U3.5(MII_TXD_2) U37.12(1Y4) ; also on sheet 10
PRUETH0_TXD3: U3.6(MII_TXD_3) U37.14(1Y3) ; also on sheet 10
PRUETH0_TXEN: TP32.1 U3.2(MII_TX_EN) U37.16(1Y2) ; also on sheet 10
PRUETH1_ACTLED: J1.12(D4) R97.1(P1) U2.26(LED_ACT)
PRUETH1_COL: R27.1(P1) U2.42(MII_COL) U7.1(A) U9.11(3B1)
PRUETH1_INTn: R18.1(P1) U2.7(PWRDNn/INTn)
PRUETH1_JTCK: TP16.1 U2.8(JTAG_TCK)
PRUETH1_JTDI: TP8.1 U2.12(JTAG_TDI)
PRUETH1_JTDO: TP14.1 U2.9(JTAG_TDO)
PRUETH1_JTMS: TP12.1 U2.10(JTAG_TMS)
PRUETH1_JTRSTn: TP10.1 U2.11(JTAG_TRSTn)
PRUETH1_LINKLED: J1.10(D2) R95.1(P1) TP17.1 U2.28(LED_LINK)
PRUETH1_RXD3: R29.1(P1) U2.46(MII_RXD_3) U11.14(4B1)
PRUETH1_RXDV: J19.2 TP36.1 U2.39(MII_RX_DV) U9.5(2B1)
PRUETH1_RXERR: R138.2(P2) U2.41(MII_RX_ERR) U7.2(B) U11.6(2B2)
PRUETH1_RXERR_COL: R138.1(P1) U7.4(Y) U11.11(3B1)
PRUETH1_SPEEDLED: D5.1(Cathode) R15.1(P1) TP40.1 U2.27(LED_SPEED) ; also on sheet 11
PRUETH1_SWSTRAP: R129.1(P1) U2.21(SW_STRAPN)
PRUETH1_TXCLK: U2.1(MII_TX_CLK) U11.2(1B1)
PRUETH1_TXD0: U2.3(MII_TXD_0) U9.2(1B1) U11.13(4B2)
PRUETH1_TXEN: TP33.1 U2.2(MII_TX_EN) U11.3(1B2) U11.5(2B1)
PRUETH_MDC: R148.1(P1) R149.1(P1) R150.1(P1) U2.31(MDC) U3.31(MDC)
PRUETH_MDIO: R145.1(P1) R146.1(P1) R147.1(P1) U2.30(MDIO) U3.30(MDIO)
PRUETHER0_RDN: J2.2 R116.2(P2) U3.13(RD-)
PRUETHER0_RDP: J2.1 R117.2(P2) U3.14(RD+)
PRUETHER0_TDN: J2.6 R118.2(P2) U3.16(TD-)
PRUETHER0_TDP: J2.5 R119.2(P2) U3.17(TD+)
PRUETHER1_RDN: J1.2 R120.2(P2) U2.13(RD-)
PRUETHER1_RDP: J1.1 R121.2(P2) U2.14(RD+)
PRUETHER1_TDN: J1.6 R122.2(P2) U2.16(TD-)
PRUETHER1_TDP: J1.5 R123.2(P2) U2.17(TD+)
RESn: J17.6 R230.2(P2)
SPI1_CS0: J3.18 ; also on sheet 10
SPI1_D0: J3.14 ; also on sheet 10
SPI1_D1: J3.16 ; also on sheet 10
SPI1_SCLK: J3.12 ; also on sheet 10
SYS_BOOT0: R57.1(P1) R157.2(P2) U37.2(1A1)
SYS_BOOT1: J5.2 U37.4(1A2)
SYS_BOOT2: R56.1(P1) R158.2(P2) U37.6(1A3)
SYS_BOOT3: R55.1 R159.2(P2) U37.8(1A4)
SYS_BOOT4: R54.1 R160.2(P2) U37.11(2A1)
SYS_BOOT5: R53.1(P1) R161.2(P2) U37.13(2A2)
SYS_BOOT6: R52.1(P1) R162.2(P2) U37.15(2A3)
SYS_BOOT7: R51.1(P1) R163.2(P2) U37.17(2A4)
SYS_BOOT8: R50.1 R164.2(P2) U38.2(1A1)
SYS_BOOT9: R49.1(P1) R165.2(P2) U38.4(1A2)
SYS_BOOT10: R47.1(P1) R167.2(P2) U38.6(1A3)
SYS_BOOT11: R45.1 R169.2(P2) U38.8(1A4)
SYS_BOOT12: R48.1(P1) R166.2(P2) U38.11(2A1)
SYS_BOOT13: R46.1(P1) R168.2(P2) U38.13(2A2)
SYS_BOOT14: R44.1 R170.2(P2) U38.15(2A3)
SYS_BOOT15: R43.1(P1) R171.2(P2) U38.17(2A4)
SYS_RESETn: R105.1(P1) R230.1(P1) U5.2(B) ; also on sheet 11 14
TESTOUT: TP24.1(TP) U14.A3(RESERVED)
UART0_RXD: R181.1 ; also on sheet 10
UART0_TXD: C184.1 R186.1 ; also on sheet 10
UART1_RXD: U28.5(R) ; also on sheet 10
UART1_TXD: U28.8(D) ; also on sheet 10
UART4_RXD_SYNC0_OUT: J3.7 ; also on sheet 10
UART4_TXD_SYNC1_OUT: J3.8 ; also on sheet 10
VADD33_PRUETH0: C2.1 C5.1 R8.1(P1) R241.1(P1) U3.22(AVDD33)
VADD33_PRUETH1: C1.1 C3.1 R7.1(P1) R240.1(P1) U2.22(AVDD33)
VAUX1: C21.1 C124.1 C132.1 R39.2(P2) U12.3(VDD) U14.N16(VDDA1P8V_USB0) U14.R16(VDDA1P8V_USB1) ; also on sheet 12
VAUX2: C23.1 C29.1 C47.1 C109.2 C110.2 C111.2 C112.1 C113.1 C137.2 C139.1 C143.2 C172.2 C173.2 C175.2 C189.1 C193.1 C201.1 C202.2 C205.1 R37.2 R43.2(P2) R44.2 R45.2 R46.2(P2) R47.2(P2) R48.2(P2) R49.2(P2) R50.2 R51.2(P2) R52.2(P2) R53.2(P2) R54.2 R55.2 R56.2(P2) R57.2(P2) U14.E10(VDDSHV6) U14.E11(VDDSHV6) U14.E12(VDDSHV6) U14.E13(VDDSHV6) U14.F14(VDDSHV6) U14.G14(VDDSHV6) U14.K14(VDDSHV5) U14.L14(VDDSHV5) U14.N5(VDDSHV6) U14.P5(VDDSHV6) U14.P6(VDDSHV6) U14.P7(VDDSHV1) U14.P8(VDDSHV1) U14.P12(VDDSHV3) U14.P13(VDDSHV3) ; also on sheet 10 11 12
VAUX33: C116.1 C120.1 C186.1 R63.2 R184.2 U14.N15(VDDA3P3V_USB0) U14.R15(VDDA3P3V_USB1) U29.10(VIN) ; also on sheet 12
VBREF: C267.1 J17.9
VCAN: J6.1 J9.9
VCAN0: C24.1(POS) C98.1 C107.1 C185.1 C191.1(POS) J6.2 J10.2 R152.2(P2) U16.8(VCC2) U27.7(OUT) U27.8(OUT) U28.16(VCC2)
VCOMH: C63.1 J17.2
VDAC: C114.1 C152.1 C177.1 C182.1 C212.1 U14.E6(VDDS) U14.E14(VDDS) U14.F9(VDDS) U14.K13(VDDS) U14.N6(VDDS) U14.P9(VDDS) U14.P14(VDDS) ; also on sheet 12
VDIG2: C106.1 C108.1 C135.1 C166.1 C181.1 C196.1 U14.D10(VDDS_SRAM_MPU_BB) U14.E7(VDDS_PLL_DDR) U14.E9(VDDS_SRAM_CORE_BG) U14.H15(VDDS_PLL_MPU) U14.R10(VDDS_PLL_CORE_LCD) U14.R11(VDDS_OSC) ; also on sheet 12
VMMC: C68.1 C119.2 C121.2 C157.2 C160.2 C179.2 C229.2 C260.1 C272.1 J16.4(VDD) R231.2(P2) R233.2(P2) R234.2(P2) R235.2(P2) R236.2(P2) R237.2(P2) U14.H14(VDDSHV4) U14.J14(VDDSHV4) U14.P10(VDDSHV2) U14.P11(VDDSHV2) U24.10(VCC) ; also on sheet 12
VPLL: FB2.2 ; also on sheet 12
VPP: U14.M5(VPP)
VPROFI_DB: J9.6 J10.1
VPROFI_SRC: C95.1 C96.1 D11.1(CATHODE) D13.1(CATHODE) U27.5(IN) U27.6(IN)
VPROFI_TRANSA: D13.2(ANODE) L1.8
VPROFI_TRANSB: D11.2(ANODE) L1.5
VRTC: C197.1 U14.D7(VDDS_RTC) ; also on sheet 11 12
VTT_DDR: C32.1 C38.1 C39.1 C41.1 C214.1 C215.1 R180.2 RP1.9 RP1.10 RP1.11 RP1.12 RP1.13 RP1.14 RP1.15 RP1.16 RP2.11 RP2.12 RP2.13 RP2.14 RP2.15 RP2.16 RP3.9 RP3.10 RP3.11 RP3.12 RP3.13 RP3.14 RP3.15 RP3.16 U29.3(VO) U29.5(VOSNS)
N16792759: R174.2(P2) U28.6(~{RE})
N16818242: C6.1 C16.1 C81.1 C82.1 U3.18(PFBIN1) U3.23(PFBOUT) U3.37(PFBIN2)
N16818333: R8.2(P2) U3.20(RSV)
N16818596: J2.9(D1) R89.1(P1)
N16819128: R10.2(P2) U3.24(RBIAS)
N17075237: D4.2(Anode) R130.1(P1)
N20350418: J5.3 R38.2(P2)
N21063525: R101.1(P1) U1.F6(~{BYTE})
N21210919: R224.2(P2) R225.1(P1) U34.4(EN)
N21210937: D20.2(ANODE) L2.2 U34.1(SW)
N21211001: C255.2 R220.1(P1) R221.2(P2) U34.3(FB)
N21251713: J2.11(D3) R93.1(P1)
N21797281: R40.2(P2) U9.15(OE#)
N21797333: R41.2(P2) U11.15(OE#)
N21800158: C162.1 R179.2 R182.2
N21868977: C216.1 R191.1 R195.2 U29.1(REFIN)
N21870936: R183.2 U15.L8(ZQ)
N21881059: D5.2(Anode) R131.1(P1)
N21881073: J1.11(D3) R98.1(P1)
N21881115: J1.9(D1) R94.1(P1)
N21881265: C4.1 C14.1 C83.1 C84.1 U2.18(PFBIN1) U2.23(PFBOUT) U2.37(PFBIN2)
N21881353: R7.2(P2) U2.20(RSV)
N21881950: R9.2(P2) U2.24(RBIAS)
N22333314: R88.2(P2) SW1.1(P0) U25.1(P0)
N22333318: R99.2(P2) SW1.2(P1) U25.2(P1)
N23086594: R13.1 U3.25(CLKOUT)
N23086888: R12.1 U2.25(CLKOUT)
N28554546: D1.2(R) R1.2(P2)
N28554548: D1.4(Y) R2.2(P2)
N28554589: Q2.3 R1.1(P1)
N28554595: Q1.6(3) R3.1(P1)
N28554605: Q1.3 R2.1(P1)
N28554613: D1.3(G) R3.2(P2)
N28559145: D2.2(R) R4.2(P2)
N28559147: D2.4(Y) R5.2(P2)
N28559250: D2.3(G) R6.2(P2)
N28559254: Q3.6(3) R4.1(P1)
N28559256: Q2.6(3) R5.1(P1)
N28559275: Q3.3 R6.1(P1)
N28559577: D3.1(Cathode) Q4.6(3)
N28559579: D3.2(Anode) R128.1(P1)
N28559581: Q4.2(5) R126.1(P1) R127.2(P2)
N28753994: R100.2(P2) SW1.4(P2) U25.3(P2)
N28754074: R87.2(P2) SW1.8(P3) U25.5(P3)
N28785526: J19.1 R112.2(P2)
N28785533: J19.3 R110.2(P2)
N28944514: J18.1 R114.2(P2)
N28944521: J18.3 R113.2(P2)
N29141166: C89.2 U12.14(XOUT) Y1.1
N29141233: C90.2 U12.1(Xin/CLK) Y1.2
N29141536: R39.1(P1) U12.2(S0)
N29149555: R42.1 U12.8(Y3)
N29149585: R154.1 U12.9(Y2)
N29149616: R144.1 U12.11(Y1)
N29208060: J5.1 R37.1

Not connected (* = marked no-connect by the designer): J1 7*; J2 7*; J9 1* 4*; J16 10(CD)*; Q4 3* 4* 5*; R212 3(SENS1)* 4(SENS2)*; R219 3(SENS1)* 4(SENS2)*; RP2 7* 8* 9* 10*; U1 B3(NC0)* C4(NC1)* D3(NC2)*; U2 33(XO)*; U3 33(XO)*; U9 12(4A)*; U12 4(Vctr)*; U15 J1(NC1)* J9(NC2)* L1(NC3)* L9(NC4)* M7(NC5)*; U24 4(NC1)* 9(NC2)*; U27 1(NC/FB)* 2(PG)*; U28 10(ISODE)*

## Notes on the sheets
sheet 1
- HOST EXPANSION HEADERS
- 5V TO 13V BOOST CONVERTER
- GPMC
- ROTARY SWITCH - INDUSTRIAL ETHERNET SLAVE ADDRESS SELECTOR
- MONOCHROME LCD INTERFACE
- MICRO SD CARD SOCKET
sheet 2
- ETHERNET 1
- ETHERNET 1
- PHYAD SETTING
sheet 3
- ETHERNET 0
- ETHERNET 0
- PHYAD SETTING
- ETHERNET 0&1 RESET
- PHY CLK IN
sheet 4
- MII1_MUX1
- MII1_MUX2
- MII0_MUX
- MII1_MUX
sheet 5
- PROFIBUS
- CAN /PROFIBUS SELECTION
- CAN PORT
sheet 6
- D FLIPFLOP
- NOR FLASH
sheet 7
- DDR3 SDRAM
- Terminations
- VTT REGULATOR
- DECAPS
- DDR3 DECAPS
- VTT REGULATOR DECAPS
sheet 8
- SYS BOOT BUFFERS
- BOOT CONFIGURATION
- Check Hardware User's Guide for Boot Sequence Details
- ETHERNET LEDS
- PROFINET Power ON
- Green1
- FET SWITCH
sheet 9
- AM335X POWER
- DECAPS
